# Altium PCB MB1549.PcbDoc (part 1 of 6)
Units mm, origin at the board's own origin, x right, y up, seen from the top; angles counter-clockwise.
Board outline 70 x 133.34 mm, 6 copper layers (Top Layer, Signal Layer 1, Signal Layer 2, Signal Layer 3, Signal Layer 4, Bottom Layer), stack 1.57 mm thick; 289 components, 250 nets, 1288 pads, 875 vias.
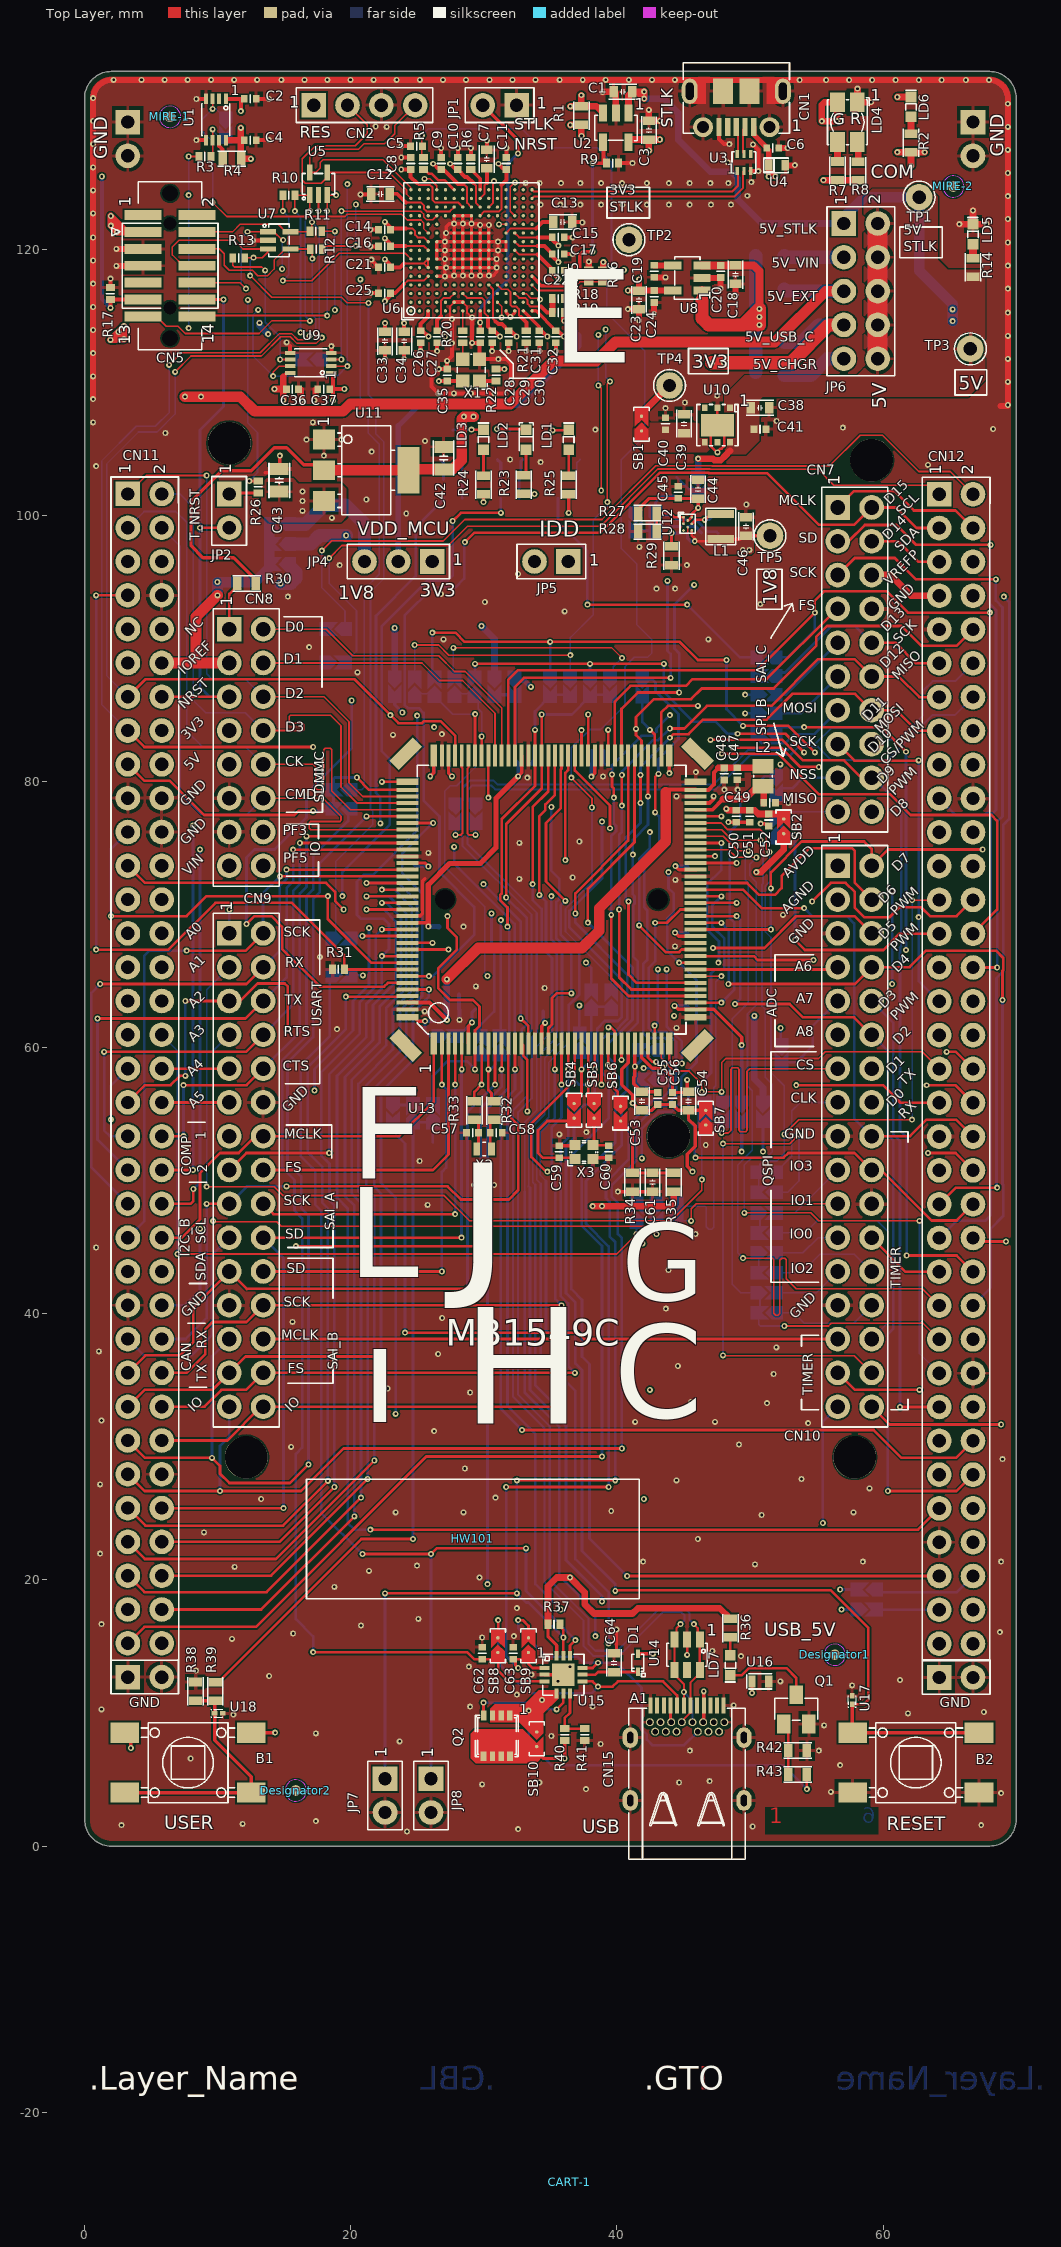
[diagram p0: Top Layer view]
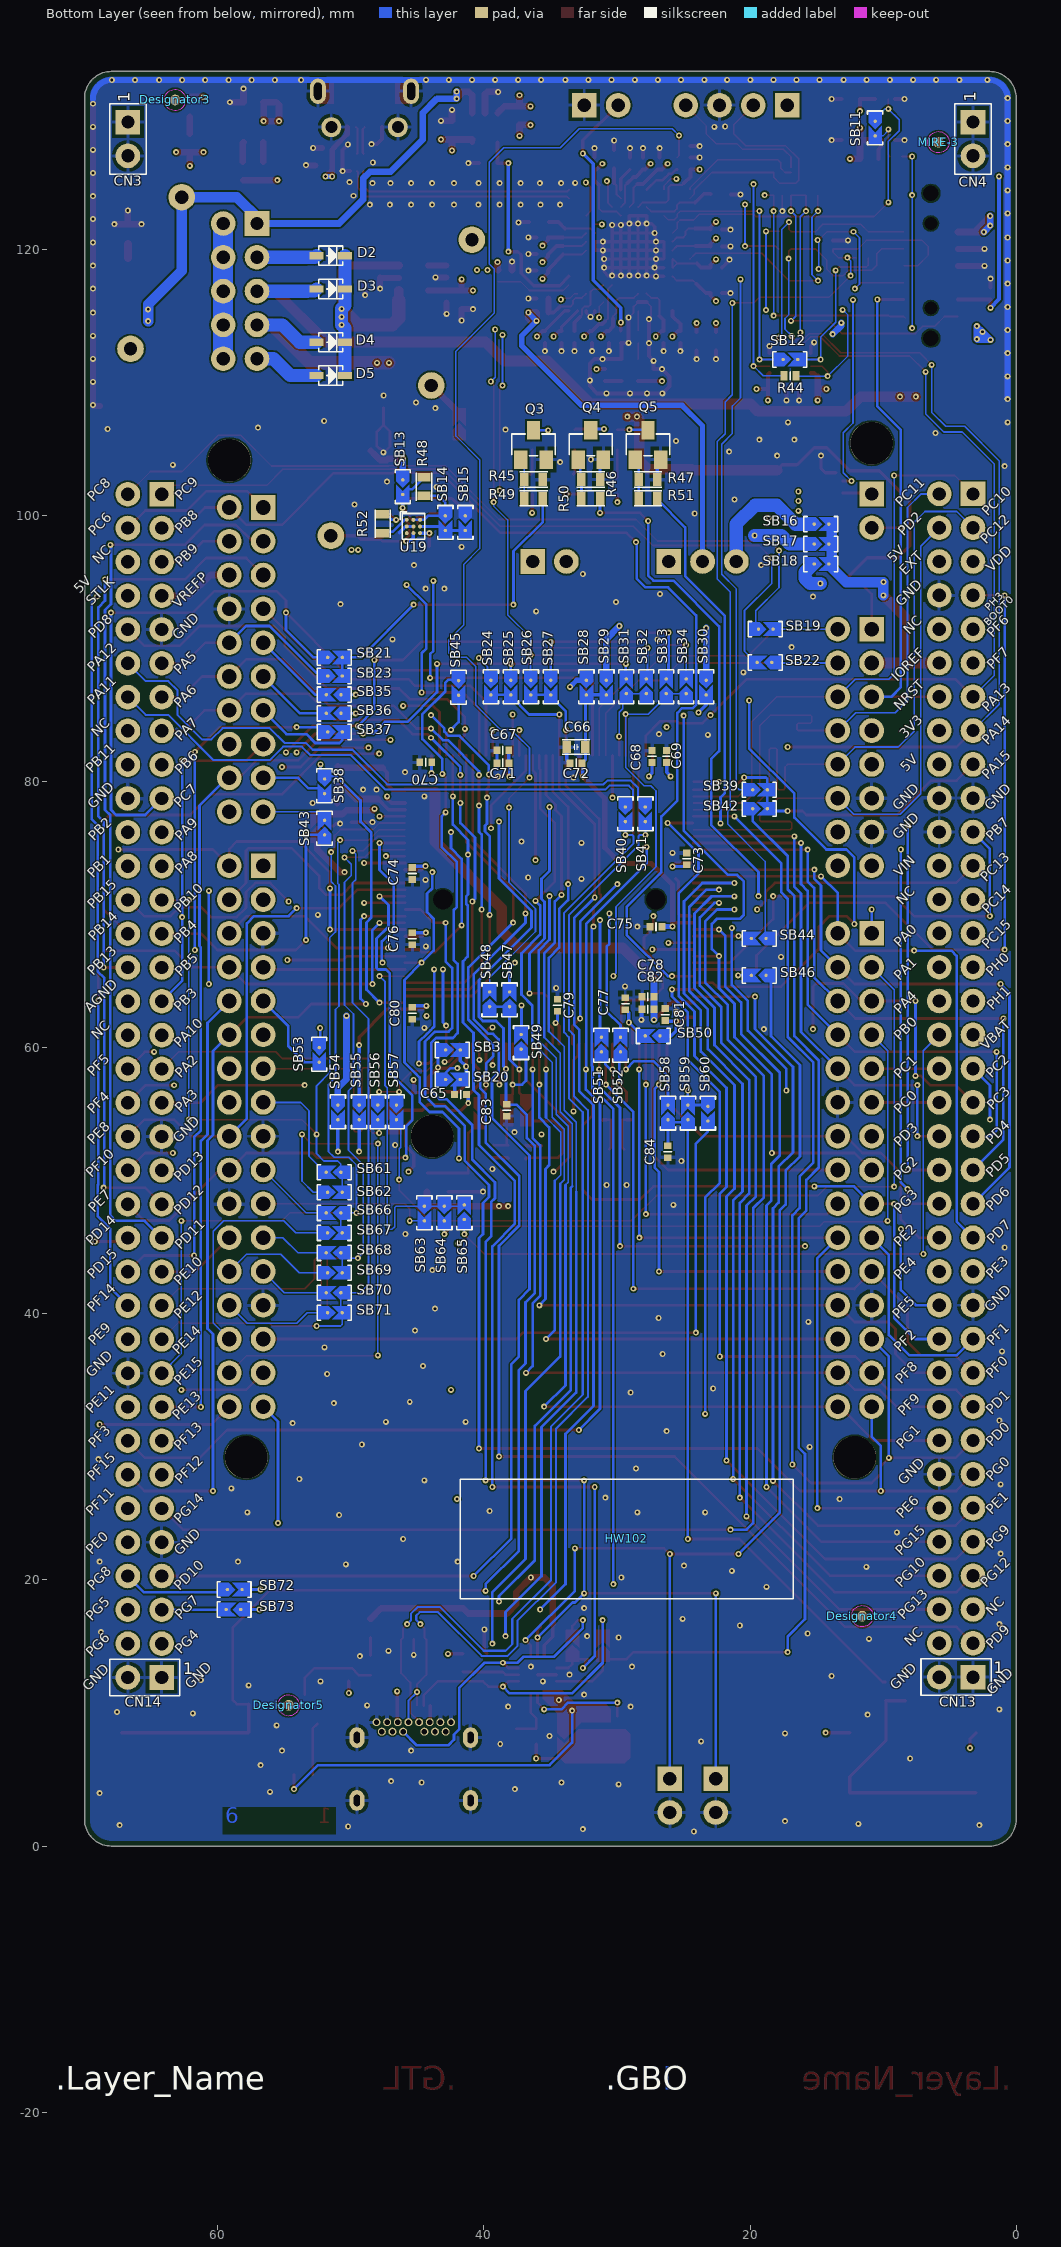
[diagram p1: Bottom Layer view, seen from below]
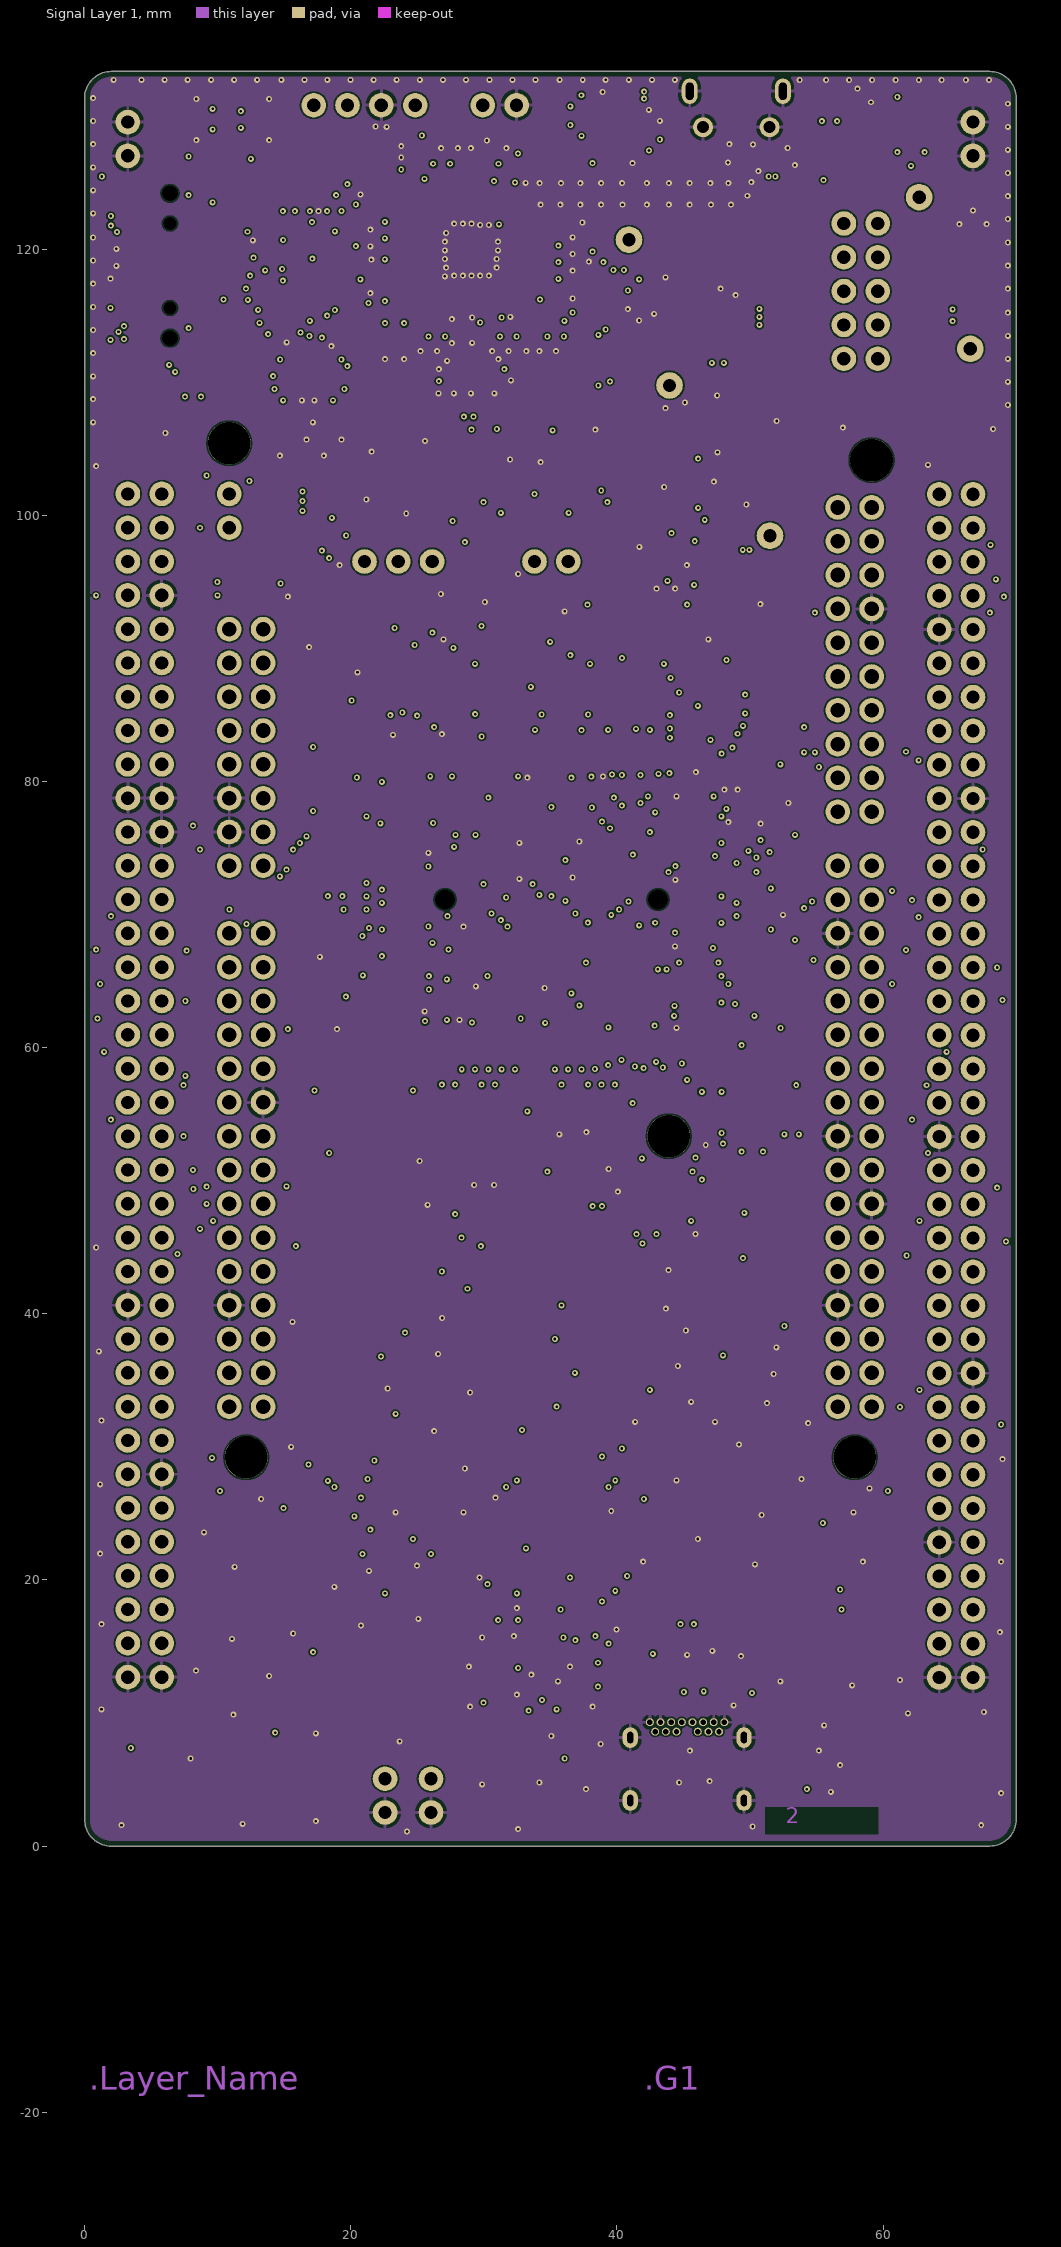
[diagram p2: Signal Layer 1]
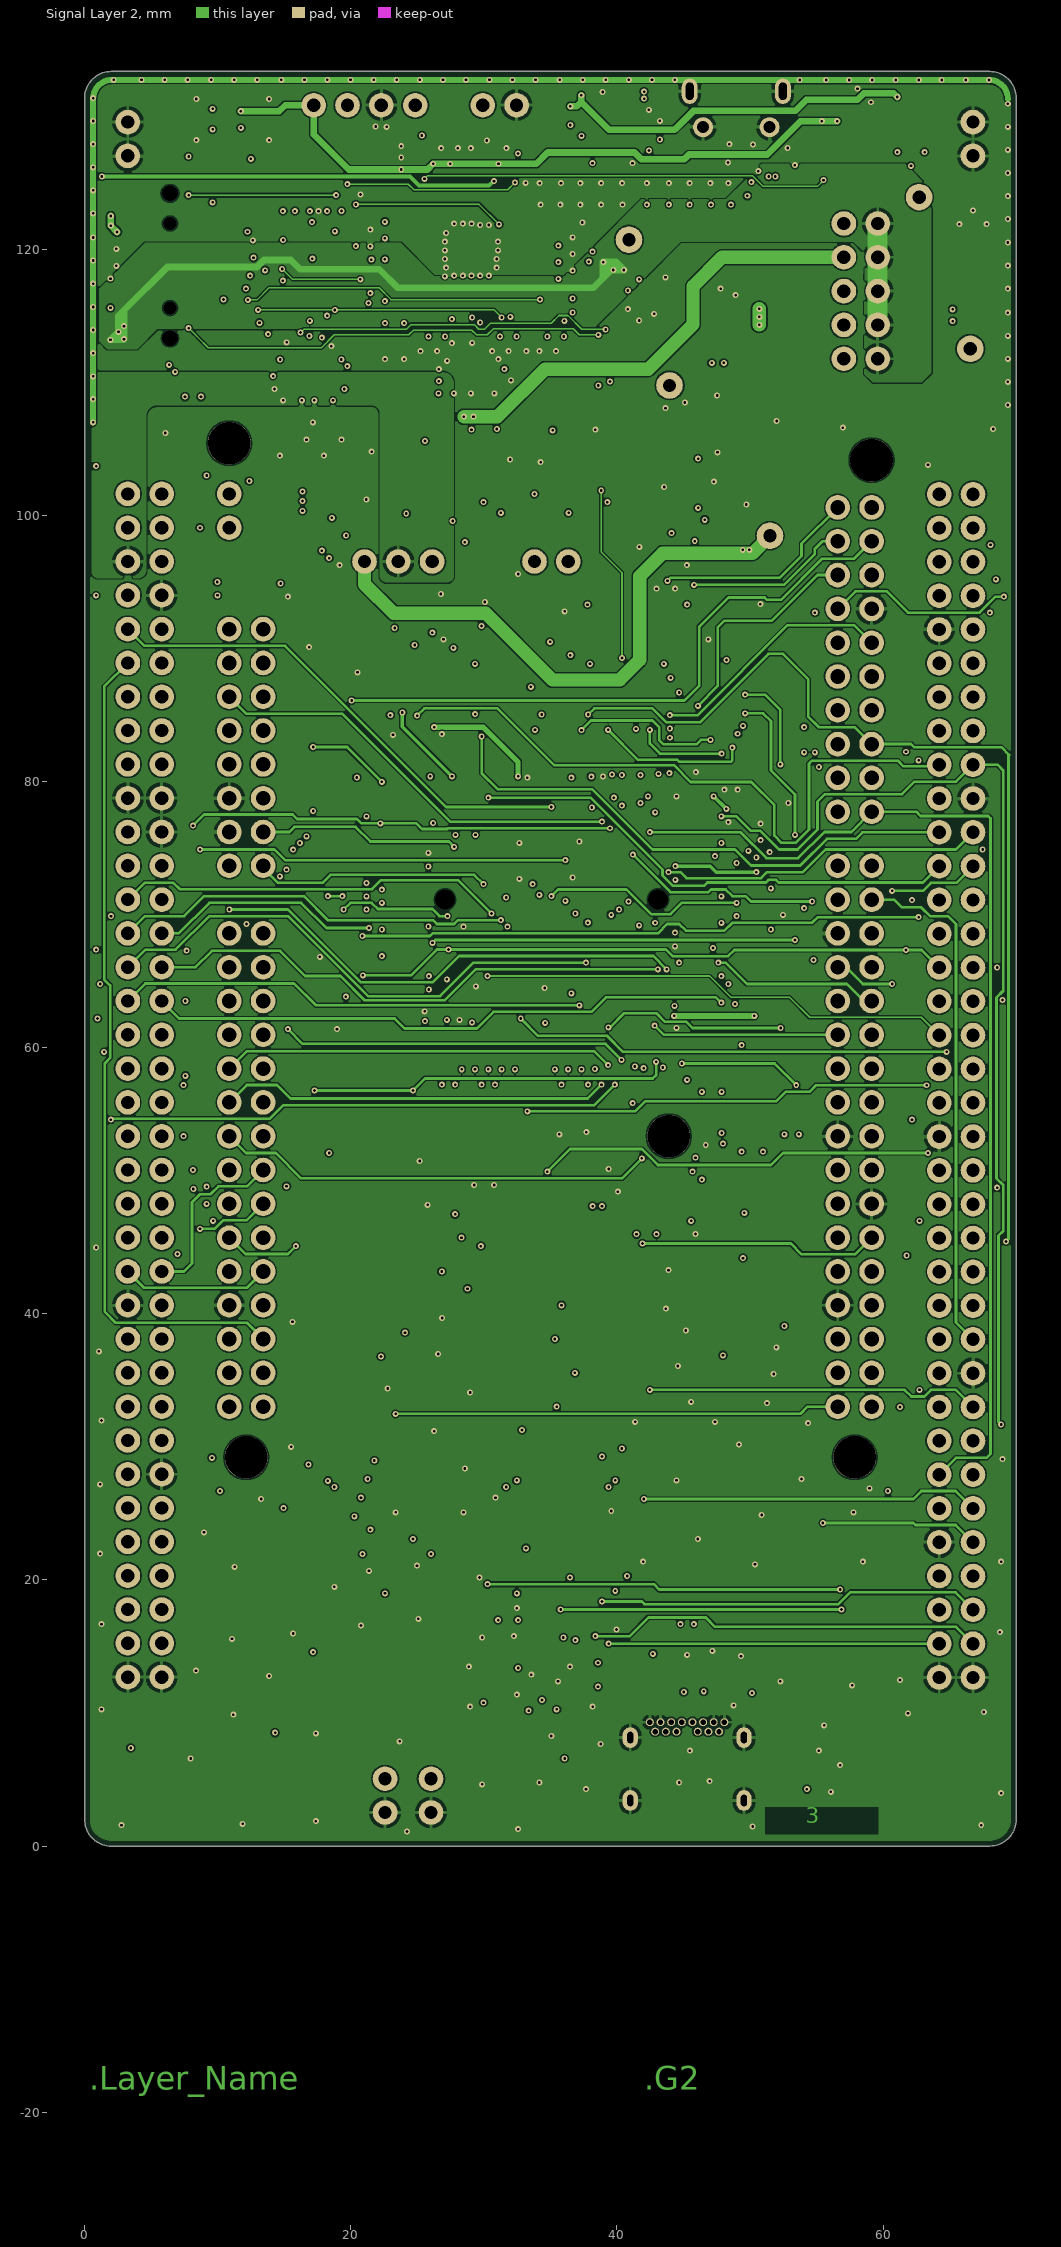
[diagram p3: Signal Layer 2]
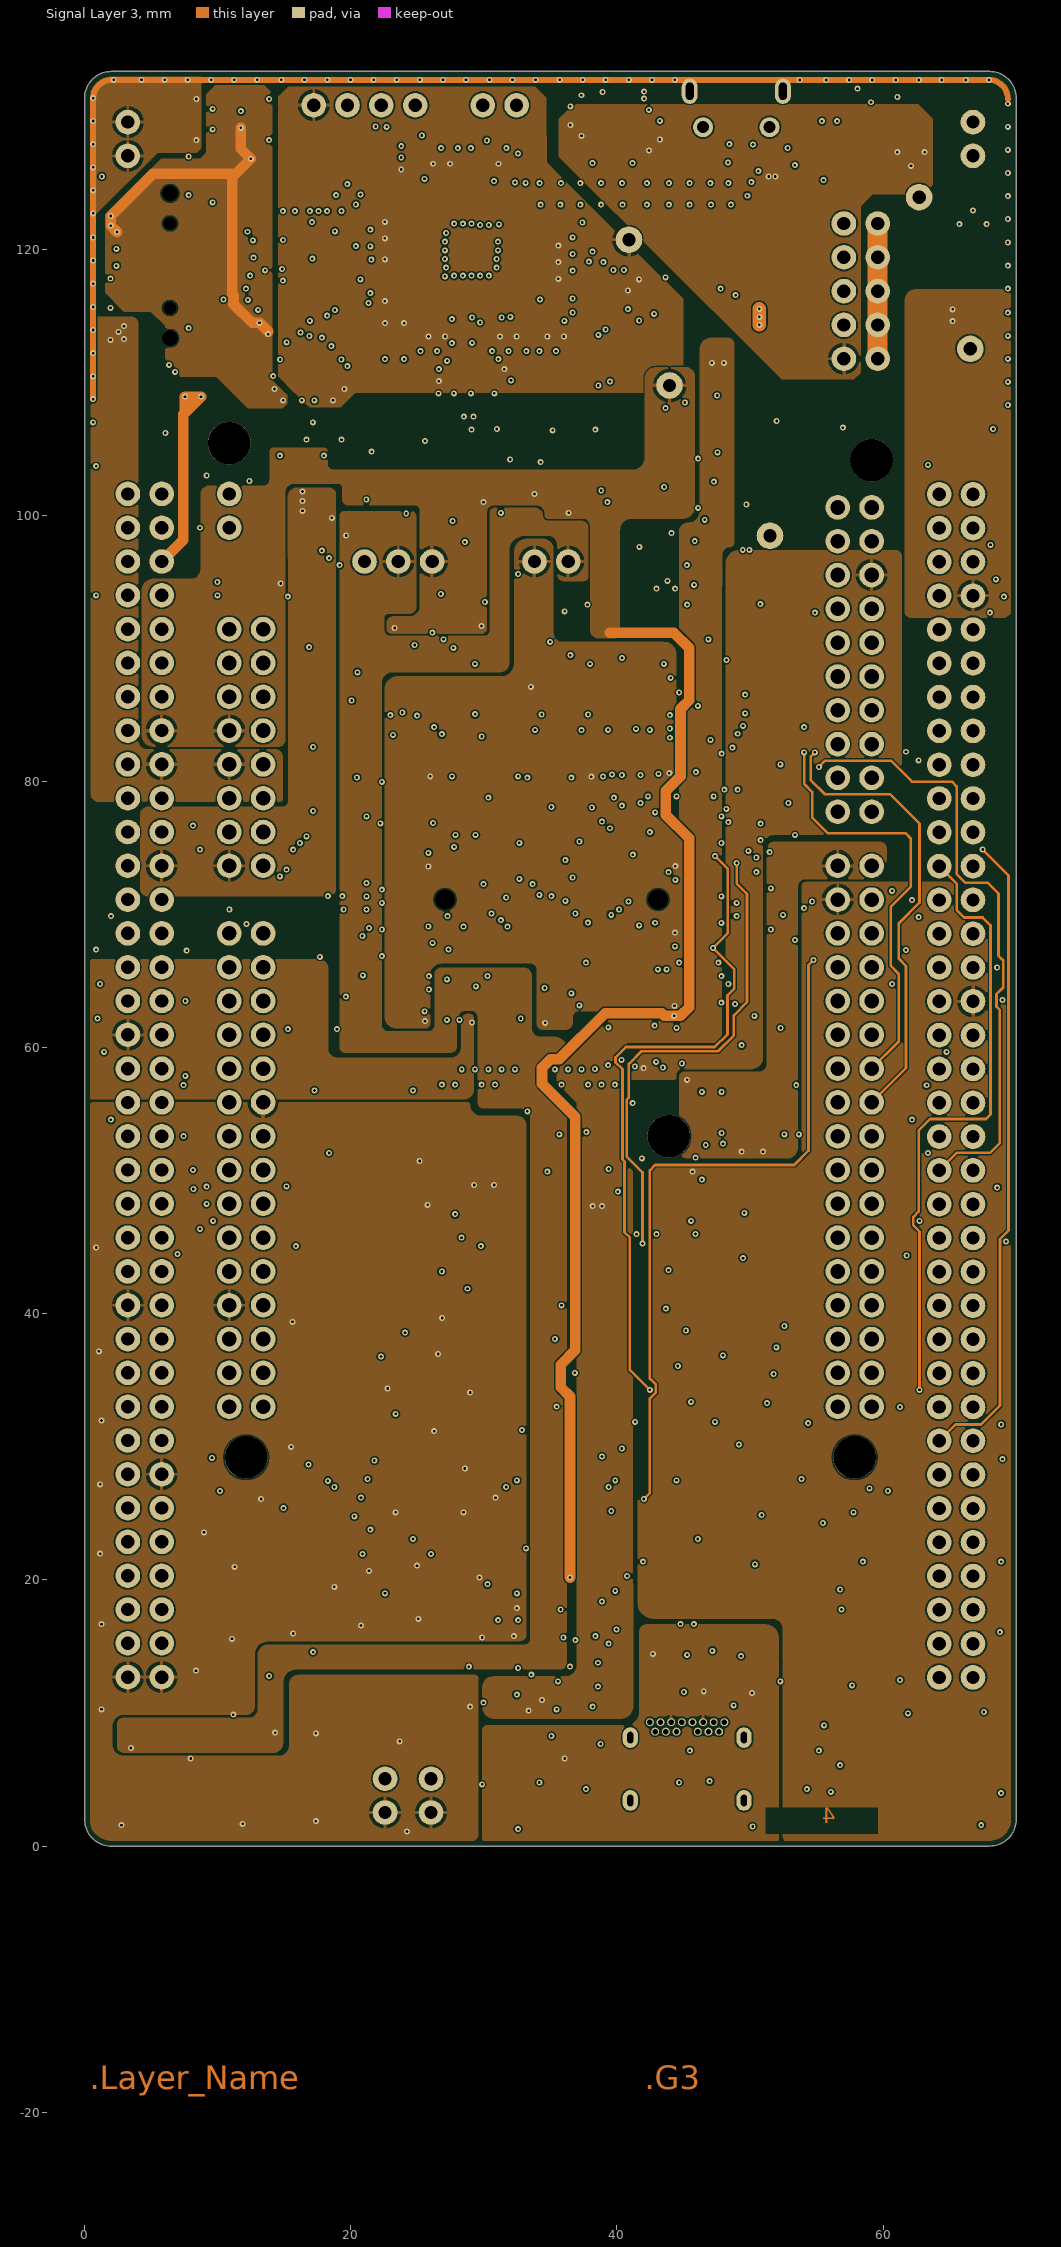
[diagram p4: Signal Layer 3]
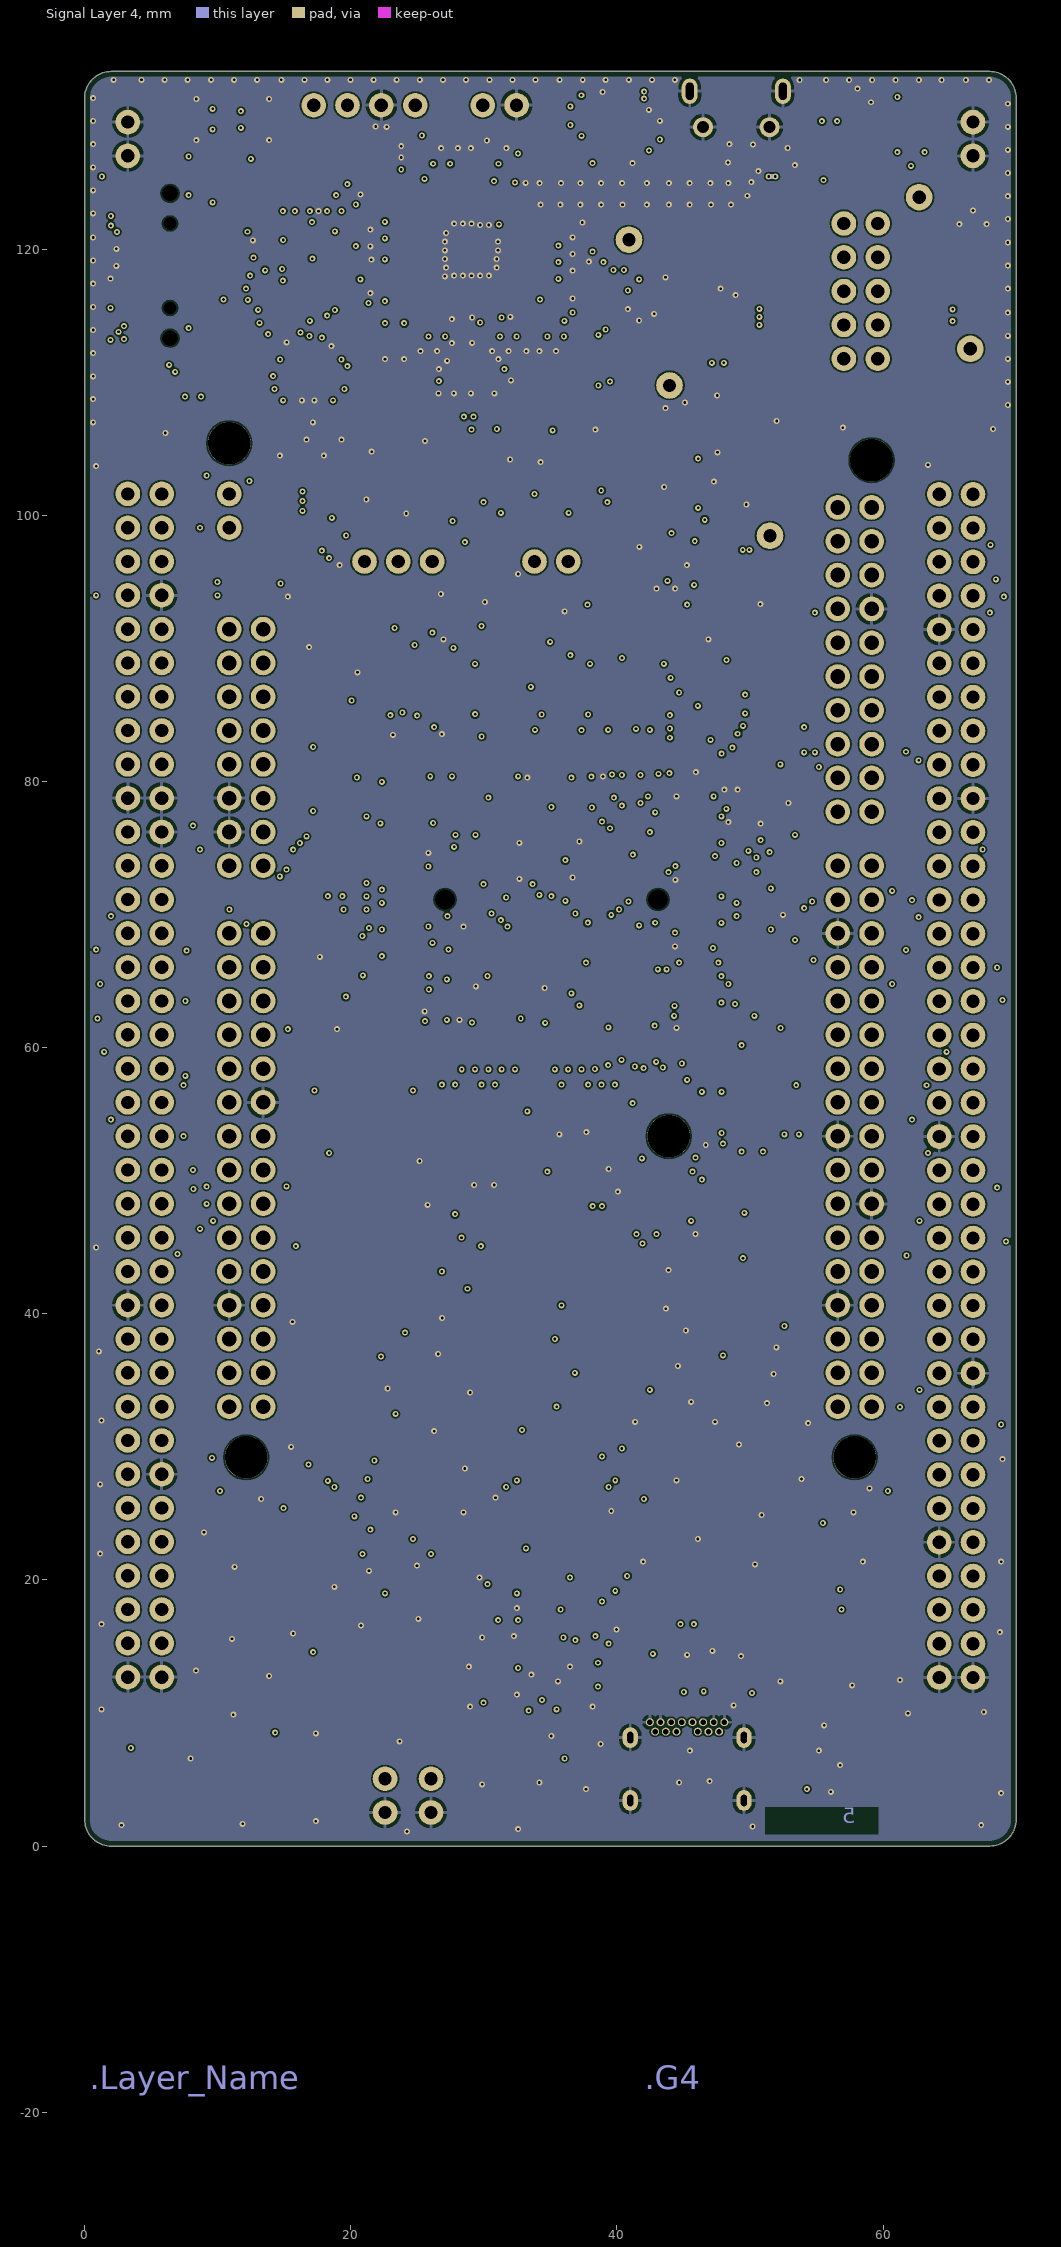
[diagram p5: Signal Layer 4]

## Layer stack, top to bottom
Top Solder: solder mask 0.015, Solder Resist, Dk 3.5
Top Layer: signal copper 0.042
Dielectric 1: core 0.09, FR-4, Dk 4.2
Signal Layer 1: signal copper 0.035
Dielectric 2: prepreg 0.1, Dk 4.2
Signal Layer 2: signal copper 0.035
Dielectric 3: core 0.966, Dk 4.2
Signal Layer 3: signal copper 0.035
Dielectric 4: prepreg 0.1, Dk 4.2
Signal Layer 4: signal copper 0.035
Dielectric 5: core 0.09, Dk 4.2
Bottom Layer: signal copper 0.042
Bottom Solder: solder mask 0.015, Solder Resist, Dk 3.5

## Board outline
0.004,2.002 ccw(c2.004,2.002) 2.004,0.002 2,0.001 68,0.001 68,0.006 ccw(c68,2.006) 70,2.006 70,131.341 ccw(c68,131.341) 68,133.341 2,133.341 ccw(c2,131.341) 0,131.341

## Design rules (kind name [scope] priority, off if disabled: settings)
BoardOutlineClearance "BOTTOM Silksreen clearence" [OnLayer('Bottom Overlay')] p1: gap=0 ignorepadtopadclearanceinfootprint=FALSE
BoardOutlineClearance "TOP Silksreen clearence" [OnLayer('Top Overlay')] p2: gap=0 ignorepadtopadclearanceinfootprint=FALSE
BoardOutlineClearance [All] p3: gap=0.4 ignorepadtopadclearanceinfootprint=FALSE
Clearance Clearance_ALIM [InNetClass('ALIM')] p1: gap=0.127 ignorepadtopadclearanceinfootprint=FALSE except(0.15: Track-Fill SMDPad-Fill THPad-Fill Via-Fill Fill-Fill; 0.2: Arc-Track Arc-THPad Track-Track Track-THPad SMDPad-SMDPad SMDPad-THPad THPad-THPad; 0.3: Track-Poly Poly-Poly)
Clearance [All] p2: gap=0.12 ignorepadtopadclearanceinfootprint=FALSE except(0.2: SMDPad-SMDPad SMDPad-THPad THPad-THPad Via-Via; 0.3: Arc-Fill Track-Fill SMDPad-Fill THPad-Fill Via-Fill Fill-Fill)
ComponentClearance [All] p1 off: gap=0.025 collisioncheckmode=3 verticalgap=2540 showdistances=TRUE
DiffPairsRouting [InDifferentialPairClass('USB')] p1: maxlimit=0.254 minlimit=0.226 mostfreqgap=0.254 toplayer_maxgap=0.226 toplayer_prefgap=0.226 toplayer_minwidth=0.155 toplayer_maxwidth=0.155 toplayer_prefwidth=0.155 midlayer1_mingap=0.254 midlayer1_minwidth=0.381 midlayer1_maxwidth=0.381 midlayer1_prefwidth=0.381 midlayer2_mingap=0.251 midlayer2_maxgap=0.251 midlayer2_prefgap=0.251 midlayer2_minwidth=0.13 midlayer2_maxwidth=0.13 midlayer2_prefwidth=0.13 midlayer3_mingap=0.254 midlayer3_minwidth=0.381 midlayer3_maxwidth=0.381 midlayer3_prefwidth=0.381 midlayer4_mingap=0.254 midlayer4_minwidth=0.381 midlayer4_maxwidth=0.381 midlayer4_prefwidth=0.381 bottomlayer_maxgap=0.226 bottomlayer_prefgap=0.226 bottomlayer_minwidth=0.155 bottomlayer_maxwidth=0.155 bottomlayer_prefwidth=0.155 maxuncoupledlength=12.7
Height [All] p1 off: minheight=0 maxheight=100 prefheight=0.5
HoleSize [All] p1: absolutevalues=TRUE maxlimit=10 minlimit=0.1 maxpercent=80.000 minpercent=20.000
HoleToHoleClearance [All] p1: gap=0.25 allowstackedmicrovias=TRUE
MatchedLengths "Schematic Matched Net Lengths_3" [InNet('USB_DEV_HS_N')] p1: tolerance=2.5 checknetsindiffpair=TRUE checkdiffpairvsdiffpair=FALSE checkxsignals=FALSE checkothers=FALSE
MatchedLengths "Schematic Matched Net Lengths_2" [InNet('USB_DEV_HS_CN_N')] p2: tolerance=0.2 checknetsindiffpair=TRUE checkdiffpairvsdiffpair=FALSE checkxsignals=FALSE checkothers=FALSE
MatchedLengths "Schematic Matched Net Lengths_1" [InNet('USB_DEV_HS_CN_P')] p3: tolerance=0.2 checknetsindiffpair=TRUE checkdiffpairvsdiffpair=FALSE checkxsignals=FALSE checkothers=FALSE
MatchedLengths "Schematic Matched Net Lengths" [InNet('USB_DEV_HS_P')] p4: tolerance=0.2 checknetsindiffpair=TRUE checkdiffpairvsdiffpair=FALSE checkxsignals=FALSE checkothers=FALSE
MatchedLengths MatchedLengths_JTAG [All] p5: tolerance=10 checknetsindiffpair=FALSE checkdiffpairvsdiffpair=TRUE checkxsignals=TRUE checkothers=TRUE
MatchedLengths MatchedLengths_USB [InDifferentialPairClass('USB')] p6: tolerance=2.5 checknetsindiffpair=FALSE checkdiffpairvsdiffpair=TRUE checkxsignals=TRUE checkothers=TRUE
MatchedLengths MatchedLengths_SD_CARD [All] p7: tolerance=10 checknetsindiffpair=FALSE checkdiffpairvsdiffpair=TRUE checkxsignals=TRUE checkothers=TRUE
MatchedLengths MatchedLengths_SPI [InNetClass('SPI')] p8: tolerance=7 checknetsindiffpair=FALSE checkdiffpairvsdiffpair=TRUE checkxsignals=TRUE checkothers=TRUE
MaxMinImpedance "Schematic Impedance Constraint_3" [InNet('USB_DEV_HS_CN_N')] p1: minimum=85,00 maximum=95,00
MaxMinImpedance "Schematic Impedance Constraint_2" [InNet('USB_DEV_HS_CN_P')] p2: minimum=85,00 maximum=95,00
MaxMinImpedance "Schematic Impedance Constraint_1" [InNet('USB_DEV_HS_N')] p3: minimum=85,00 maximum=95,00
MaxMinImpedance "Schematic Impedance Constraint" [InNet('USB_DEV_HS_P')] p4: minimum=85,00 maximum=95,00
MinimumSolderMaskSliver [All] p1: minsoldermaskwidth=0
PlaneClearance [All] p1: clearance=0.5
PlaneConnect [All] p1: planeconnectstyle=Relief reliefexpansion=0.5 reliefentries=4 reliefconductorwidth=0.25 reliefairgap=0.25
PolygonConnect PolygonConnect_NO_TH [IsNamedPolygon('NO_TH')] p1: thpad.connectstyle=Relief thpad.reliefconductorwidth=0.25 thpad.reliefentries=4 thpad.polygonreliefangle="90 Angle" thpad.airgapwidth=0.25 smdpad.connectstyle=Direct smdpad.reliefconductorwidth=0.254 smdpad.reliefentries=4 smdpad.polygonreliefangle="90 Angle" smdpad.airgapwidth=0.254 via.connectstyle=Direct via.reliefconductorwidth=0.254 via.reliefentries=4 via.polygonreliefangle="90 Angle" via.airgapwidth=0.254
PolygonConnect PolygonConnect_1 [All] p2: thpad.connectstyle=Relief thpad.reliefconductorwidth=0.254 thpad.reliefentries=4 thpad.polygonreliefangle="90 Angle" thpad.airgapwidth=0.254 smdpad.connectstyle=Relief smdpad.reliefconductorwidth=0.254 smdpad.reliefentries=4 smdpad.polygonreliefangle="90 Angle" smdpad.airgapwidth=0.254 via.connectstyle=Direct via.reliefconductorwidth=0.254 via.reliefentries=4 via.polygonreliefangle="90 Angle" via.airgapwidth=0.254
RoutingVias [All] p1: holewidth=0.2 width=0.45 viastyle="Through Hole" minholewidth=0.2 minwidth=0.45 maxholewidth=0.2 maxwidth=0.45
SilkToSilkClearance [All] p1: silktosilkclearance=0
SilkToSolderMaskClearance [IsPad] p1: minsilkscreentomaskgap=0 clearancetoexposedcopper=TRUE
SolderMaskExpansion [All] p1: expansion=0.102 istentingtop=FALSE
Width Width_50_ohms [InNetClass('50 ohms')] p1: maxlimit=0.25 minlimit=0.102 preferedwidth=0.25 toplayer_minwidth=0.127 toplayer_maxwidth=0.127 toplayer_prefwidth=0.127 midlayer1_minwidth=0.25 midlayer2_maxwidth=0.102 midlayer2_prefwidth=0.102 midlayer3_minwidth=0.25 midlayer4_minwidth=0.25 bottomlayer_minwidth=0.127 bottomlayer_maxwidth=0.127 bottomlayer_prefwidth=0.127 minimp=50.000000 maximp=50.000000 favimp=50.000000
Width Width_GND [InNetClass('GND')] p2: maxlimit=0.8 minlimit=0.19 preferedwidth=0.25 minimp=50.000000 maximp=50.000000 favimp=50.000000
Width Width_ALIM_150mA [InNetClass('ALIM_150mA')] p3: maxlimit=1 minlimit=0.25 preferedwidth=0.8 minimp=50.000000 maximp=50.000000 favimp=50.000000
Width Width_ALIM_200mA [InNetClass('ALIM_200mA')] p4: maxlimit=1 minlimit=0.25 preferedwidth=0.4 minimp=50.000000 maximp=50.000000 favimp=50.000000
Width Width_ALIM_500mA [InNetClass('ALIM_500mA')] p5: maxlimit=1 minlimit=0.25 preferedwidth=1 minimp=50.000000 maximp=50.000000 favimp=50.000000
Width Width_ALIM_1A [InNetClass('ALIM_1A')] p6: maxlimit=2 minlimit=0.25 preferedwidth=2 minimp=50.000000 maximp=50.000000 favimp=50.000000
Width Width_1 [All] p7: maxlimit=10 minlimit=0.12 preferedwidth=0.12 minimp=50.000000 maximp=50.000000 favimp=50.000000
20 further rules are at their usual default settings.

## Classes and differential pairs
net class PC[0..15]: PC0 PC1 PC2 PC3 PC6 PC7 PC8 PC9 PC10 PC11 PC12 PC13 PC14 PC15
net class PE[0..15]: PE0 PE1 PE2 PE3 PE4 PE5 PE6 PE7 PE8 PE9 PE10 PE11 PE12 PE13 PE14 PE15
polygon class POLY_DIRECT_ALL: NETC906_2_L01_P192
component class U_ARDUINO_extension_connectors: C65 CN7 CN8 CN9 CN10 CN11 CN12 CN13 CN14 HW25 HW26 LD1 Q3 R25 R30 R45 R49 SB16 SB17 SB18 SB19 SB20 SB21 SB22 SB23 SB35 SB36 SB37 SB38 SB43 SB47 SB53 SB56 SB57 SB60 SB61 SB62 SB63 SB64 SB65 SB66 SB67 SB68 SB69 SB70 SB71 SB72
component class U_POWER_BOARD: C38 C39 C40 C41 C42 C43 C44 C45 C46 JP4 JP6 L1 LD5 R14 R27 R28 R29 R48 R52 SB1 SB13 SB14 SB15 SB116 TP3 TP4 TP5 U10 U11 U12 U19
component class U_ST_LINK_V3E: C1 C2 C3 C4 C5 C6 C7 C8 C9 C10 C11 C12 C13 C14 C15 C16 C17 C18 C19 C20 C21 C22 C23 C24 C25 C26 C27 C28 C29 C30 C31 C32 C33 C34 C35 C36 C37 CN1 CN2 CN3 CN4 CN5 D2 D3 D4 D5 D7 HW8 HW9 JP1 JP2 LD4 LD6 R1 R2 R3 R4 R5 R6 R7 R8 R9 R10 R11 R12 R13 R15 R16 R17 R18 R19 R20 R21 R22 R26 R44 SB11 SB12 TP1 TP2 U1 U2 U3 U4 U5 U6 U7 U8 U9 X1
component class U_STM32_microcontroller_IOs: B1 B2 C57 C58 C59 C60 C83 C84 HW11 HW17 HW18 LD2 LD3 Q4 Q5 R23 R24 R31 R32 R33 R38 R39 R46 R47 R50 R51 SB4 SB5 SB6 SB24 SB25 SB26 SB27 SB31 SB32 SB33 SB34 SB39 SB40 SB41 SB42 SB44 SB47 SB48 SB49 SB51 SB52 SB58 SB60 U13 U17 U18 X2 X3
component class U_STM32_microcontroller_power: C47 C48 C49 C50 C51 C52 C53 C54 C55 C56 C66 C67 C68 C69 C70 C71 C72 C73 C74 C75 C76 C77 C78 C79 C80 C81 C82 JP5 L2 SB2 SB3 SB7 SB28 SB29 SB30 SB52 SB54 SB57
component class U_USB_Type_C: C61 C62 C63 C64 CN15 D1 HW23 HW24 LD7 Q1 Q2 R34 R35 R36 R37 R40 R41 R42 R43 R108 SB8 SB9 SB10 U14 U15 U16
component class U_MB1549_Top: HW100 HW101 HW102
net class PA[0..15]: PA0 PA1 PA2 PA3 PA4 PA5 PA6 PA7 PA8 PA9 PA10 PA11 PA12 PA13 PA14 PA15
net class PB[0..15]: PB0 PB1 PB2 PB3 PB4 PB5 PB6 PB7 PB8 PB9 PB10 PB11 PB12 PB13 PB14 PB15
net class PD[0..15]: PD0 PD1 PD2 PD3 PD4 PD5 PD6 PD7 PD8 PD9 PD10 PD11 PD12 PD13 PD14 PD15
net class PF[0..15]: PF0 PF1 PF2 PF3 PF4 PF5 PF6 PF7 PF8 PF9 PF10 PF11 PF12 PF13 PF14 PF15
net class PG[0..15]: PG0 PG1 PG2 PG3 PG4 PG5 PG6 PG7 PG9 PG10 PG11 PG12 PG13 PG14 PG15
net class PH[0..3]: PH0 PH1 PH2 PH3
differential pair USB_FS: +USB_FS_P -USB_FS_N
differential pair USB_DEV_HS_CN: +USB_DEV_HS_CN_P -USB_DEV_HS_CN_N
differential pair USB_DEV_HS: +USB_DEV_HS_P -USB_DEV_HS_N

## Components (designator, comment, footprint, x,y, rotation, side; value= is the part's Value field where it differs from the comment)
B1 "" SWI_WEALTHMETAL_TD-0341_4P_BLUE 7.771,6.275 r270 top value=SW_BLUE
B2 "" SWI_WEALTHMETAL_TD-0341_4P_BLACK 62.457,6.275 r270 top value=SW_BLACK
C1 "Capacitor" C0603 40.448,131.82 r0 top value=1uF
C2 "" C0402 12.441,131.279 r180 top value=100nF
C3 "Capacitor" C0603 42.396,128.927 r270 top value=1uF
C4 "" C0402 12.441,128.179 r0 top value=100nF
C5 "Capacitor" C0402 24.941,127.729 r0 top value=20pF
C6 "Capacitor" C0402 51.699,127.593 r180 top value=100pF
C7 "Capacitor" C0603 30.216,126.754 r270 top value=2.2uF
C8 "" C0402 24.491,126.429 r270 top value=100nF
C9 "" C0402 26.791,126.429 r270 top value=100nF
C10 "" C0402 28.041,126.429 r270 top value=100nF
C11 "" C0402 31.691,126.429 r270 top value=100nF
C12 "Capacitor" C0603 22.225,124.125 r0 top value=2.2uF
C13 "Capacitor" C0603 35.925,122.025 r180 top value=2.2uF
C14 "" C0402 22.541,121.454 r0 top value=100nF
C15 "" C0402 35.591,120.879 r180 top value=100nF
C16 "" C0402 22.541,120.204 r0 top value=100nF
C17 "" C0402 35.591,119.629 r180 top value=100nF
C18 "Capacitor" C0603 48.916,118.079 r90 top value=1uF
C19 "Capacitor" C0402 42.791,118.329 r90 top value=10nF
C20 "" C0402 47.794,118.32 r90 top value=100nF
C21 "" C0402 22.541,118.629 r0 top value=100nF
C22 "" C0402 35.591,118.379 r180 top value=100nF
C23 "Capacitor" C0603 41.666,116.179 r90 top value=1uF
C24 "" C0402 42.791,116.429 r90 top value=100nF
C25 "" C0402 22.541,116.679 r0 top value=100nF
C26 "" C0402 25.241,113.404 r90 top value=100nF
C27 "" C0402 26.491,113.404 r90 top value=100nF
C28 "" C0402 29.716,113.404 r90 top value=100nF
C29 "" C0402 30.616,113.404 r90 top value=100nF
C30 "" C0402 31.866,113.404 r90 top value=100nF
C31 "" C0402 34.166,113.404 r90 top value=100nF
C32 "" C0402 35.416,113.404 r90 top value=100nF
C33 "Capacitor" C0603 22.566,113.079 r90 top value=4.7uF
C34 "Capacitor" C0603 24.016,113.079 r90 top value=1uF
C35 "" C0402 27.241,110.529 r270 top value=100nF
C36 "" C0402 15.616,109.479 r0 top value=100nF
C37 "" C0402 17.966,109.479 r0 top value=100nF
C38 "Capacitor" C0603 50.745,108.071 r180 top value=1uF
C39 "Capacitor" C0603 45.045,106.871 r270 top value=1uF
C40 "" C0402 43.645,106.871 r270 top value=100nF
C41 "" C0402 50.745,106.471 r180 top value=100nF
C42 "" C0805 26.974,104.294 r270 top value=10uF
C43 "" C0805 14.629,102.617 r270 top value=10uF
C44 "" C0603 46.095,101.956 r270 top value=10uF
C45 "" C0402 44.6,101.725 r270 top value=100nF
C46 "" C0603 49.695,99.156 r270 top value=10uF
C47 "Capacitor" C0402 49.05,80.575 r90 top value=2.2uF
C48 "Capacitor" C0402 48.05,80.561 r90 top value=2.2uF
C49 "" C0402 51.47,78.381 r180 top value=100pF
C50 "" C0402 48.97,77.381 r90 top value=10uF
C51 "" C0402 49.97,77.381 r90 top value=10uF
C52 "" C0402 51.4,77.1 r90 top value=100nF
C53 "Capacitor" C0603 41.87,55.981 r270 top value=1uF
C54 "Capacitor" C0603 45.37,55.981 r270 top value=1uF
C55 "" C0402 43.07,56.181 r90 top value=100nF
C56 "" C0402 44.17,56.181 r90 top value=100nF
C57 "Capacitor" C0402 29.15,53.6 r180 top value=1.3pF
C58 "Capacitor" C0402 30.925,53.6 r0 top value=1.3pF
C59 "Capacitor" C0402 35.67,52.181 r90 top value=6.8pF
C60 "Capacitor" C0402 39.37,52.181 r270 top value=6.8pF
C61 "" C0603 42.67,49.881 r90 top value=10pF
C62 "Capacitor" C0402 29.875,14.5 r270 top value=330pF
C63 "Capacitor" C0402 32.2,14.5 r270 top value=330pF
C64 "Capacitor" C0603 39.77,13.781 r270 top value="100nF, 50V"
C65 "" C0402 41.75,56.475 r0 bottom value=100nF
C66 "Capacitor" C0603 33.07,82.581 r180 bottom value=4.7uF
C67 "" C0402 38.575,82.325 r180 bottom value=10uF
C68 "" C0402 27.37,81.881 r270 bottom value=100nF
C69 "" C0402 26.27,81.881 r270 bottom value=100nF
C70 "" C0402 44.375,81.425 r180 bottom value=100nF
C71 "" C0402 38.57,81.381 r180 bottom value=100nF
C72 "" C0402 33.07,81.381 r180 bottom value=100nF
C73 "" C0402 24.77,74.181 r270 bottom value=100nF
C74 "" C0402 45.37,73.081 r90 bottom value=100nF
C75 "" C0402 27.07,69.081 r180 bottom value=100nF
C76 "" C0402 45.37,68.181 r90 bottom value=100nF
C77 "" C0402 29.375,63.3 r270 bottom value=100nF
C78 "Capacitor" C0402 27.675,63.825 r180 bottom value=2.2uF
C79 "" C0402 34.47,63.181 r270 bottom value=100nF
C80 "" C0402 45.37,62.581 r90 bottom value=100nF
C81 "" C0402 26.37,62.481 r270 bottom value=100nF
C82 "Capacitor" C0402 27.675,62.875 r180 bottom value=2.2uF
C83 "" C0402 38.279,55.296 r90 bottom value=100nF
C84 "" C0402 26.17,52.181 r90 bottom value=100nF
CART-1 "Comment" Sheetbox_6L2S -8.63,-30.519 r0 top
CN1 "USB_uB_105017.0001" CON_USBMICROB_MOLEX_105017-0001_H2P90 48.966,133.308 r180 top value=USB_uB_105017-0001
CN2 "Header 4x1" CON_SAMTEC_TSW-104-07-G-S 21.026,130.809 r0 top
CN3 "Jumper_Header 2x1" CON_SAMTEC_TSW-102-09-X-S 66.746,128.269 r270 bottom value="Header 2x1 16mm"
CN4 "Jumper_Header 2x1" CON_SAMTEC_TSW-102-09-X-S 3.246,128.269 r270 bottom value="Header 2x1 16mm"
CN5 "Header 7x2" CON_STDC14_Receiver_MEDIUM_WITH_MIPI10_3D 6.421,118.744 r270 top value="MIPI10 on STDC14 footprint"
CN7 "" CON_SAMTEC_SSW-110-23-X-D_N144_ARD 57.86,89.155 r90 top value="Socket 10x2_N144_ARD"
CN8 "" CON_SAMTEC_SSW-108-23-X-D_N144_ARD 12.14,82.551 r90 top value="Socket 8x2_N144_ARD"
CN9 "" CON_SAMTEC_SSW-115-23-X-D_N144_ARD 12.14,50.801 r90 top value="Socket 15x2_N144_ARD"
CN10 "" CON_SAMTEC_SSW-117-23-X-D_N144_ARD 57.86,53.341 r90 top value="Socket 17x2_N144_ARD"
CN11 "Header 35x2" CON_SAMTEC_TSW-135-07-X-D 4.52,58.421 r270 top
CN12 "Header 35x2" CON_SAMTEC_TSW-135-07-X-D 65.48,58.396 r270 top
CN13 "" CON_SAMTEC_TSW-102-09-X-S 4.52,12.701 r0 bottom value="Header 2x1 16mm"
CN14 "" CON_SAMTEC_TSW-102-09-X-S 65.48,12.676 r0 bottom value="Header 2x1 16mm"
CN15 "USB_TYPE_C_Receptacle_317JD24BZTF3K3C3" CON_USB-TYPEC_COXOC_317JD24BZTF3K3C3 45.27,-0.019 r0 top value=317JD24BZTF3K3C3
D1 "SCHOTTKY_1A_2K" DIO_SOD523_1A_2K 41.57,13.781 r270 top value=BAT54KFILM
D2 "BAT60JFILM" DIO_SOD323 51.5,119.5 r180 bottom
D3 "BAT60JFILM" DIO_SOD323 51.5,117 r180 bottom
D4 "BAT60JFILM" DIO_SOD323 51.5,113 r180 bottom
D5 "BAT60JFILM" DIO_SOD323 51.5,110.5 r180 bottom
Designator1 "Comment" MIRE_PLACE_SMD_0P8MM 56.37,14.381 r0 top
Designator2 "Comment" MIRE_PLACE_SMD_0P8MM 15.87,4.181 r0 top
Designator3 "Comment" MIRE_PLACE_SMD_0P8MM 63.2,131.2 r180 bottom
Designator4 "Comment" MIRE_PLACE_SMD_0P8MM 11.57,17.281 r180 bottom
Designator5 "Comment" MIRE_PLACE_SMD_0P8MM 54.67,10.581 r180 bottom
HW101 "STICKER_BOARD_REF" STICKER_25X9 29.17,23.081 r0 top value="MBxxxxy-zz syywwxxxxx"
HW102 "STICKER_BOARD_CPN" STICKER_25X9 29.27,23.081 r180 bottom value="Board CPN"
JP1 "Jumper_Header 2x1" CON_SAMTEC_TSW-102-07-G-S 31.186,130.809 r180 top value="Shunt not fitted"
JP2 "Jumper_Header 2x1 Fitted" CON_SAMTEC_TSW-102-07-G-S 10.866,100.329 r270 top value="Shunt Fitted"
JP4 "" CON_SAMTEC_TSW-103-07-F-S 23.57,96.521 r180 top value="Shunt Fitted 1-2"
JP5 "" CON_SAMTEC_TSW-102-07-G-S 35.07,96.521 r180 top value="Shunt Fitted"
JP6 "" CON_SAMTEC_TSW-105-07-X-D 58.32,116.839 r270 top value="Shunt Fitted 1-2"
JP7 "Jumper_Header 2x1" CON_SAMTEC_TSW-102-07-G-S 22.575,3.8 r270 top value="Shunt not fitted"
JP8 "Jumper_Header 2x1" CON_SAMTEC_TSW-102-07-G-S 26.025,3.8 r270 top value="Shunt not fitted"
L1 "" IND_TDK_VLS252010HBX-1 47.795,99.156 r270 top value="2.2uH 2.6A 0.100R"
L2 "Inductor" L0805_H0P9 50.97,80.381 r270 top value=2.2uH
LD1 "" LED_0603_GREEN 36.37,105.681 r90 top value=GREEN
LD2 "" LED_0603_VISHAY_VLMB1300-GS08_BLUE_1A2K_H0P8 33.17,105.681 r90 top value=BLUE
LD3 "LED_red" LED_0603_RED 29.97,105.681 r90 top value=RED
LD4 "LD_BICOLOR_CMS" LED_BI-GR_HSMF-A201-A00J1 57.316,129.529 r180 top
LD5 "" LED_0603_GREEN 66.746,121.119 r90 top value=GREEN
LD6 "LED_red" LED_0603_RED 62.091,130.679 r90 top value=RED
LD7 "" LED_0603_GREEN 48.52,13.581 r270 top value=GREEN
MIRE-1 "Comment" MIRE_PLACE_SMD_0P8MM 6.416,129.929 r0 top
MIRE-2 "Comment" MIRE_PLACE_SMD_0P8MM 65.275,124.7 r0 top
MIRE-3 "Comment" MIRE_PLACE_SMD_0P8MM 5.841,128.029 r180 bottom
Q1 "" NPN_SOT23 53.47,10.281 r0 top value=9013-SOT23
Q2 "STL11N3LLH6" MOS_POWERFLAT_3P3X3P3_P065 30.97,8.281 r180 top
Q3 "" NPN_SOT23 36.27,105.281 r180 bottom value=9013-SOT23
Q4 "" NPN_SOT23 31.97,105.281 r180 bottom value=9013-SOT23
Q5 "" NPN_SOT23 27.67,105.281 r180 bottom value=9013-SOT23
R1 "Resistor" R0603 37.325,130.029 r270 top value=100K
R2 "Resistor" R0603 62.091,127.979 r270 top value=1K
R3 "Resistor" R0402 9.041,126.954 r0 top value=47R
R4 "Resistor" R0603 11.066,126.779 r0 top value=100K
R5 "Resistor" R0402 25.466,126.429 r90 top value=100R
R6 "Resistor" R0402 29.016,126.429 r270 top value=3K
R7 "Resistor" R0603 56.566,125.877 r270 top value=330R
R8 "Resistor" R0603 58.116,125.852 r270 top value=330R
R9 "Resistor" R0402 39.673,126.459 r0 top value=10K
R10 "Resistor" R0402 15.35,124.05 r0 top value=47R
R11 "Resistor" R0402 17.375,121.325 r0 top value=47R
R12 "Resistor" R0402 17.4,119.975 r180 top value=47R
R13 "Resistor" R0402 11.575,119.325 r180 top value=47R
R14 "" R0603 66.746,118.619 r270 top value=1K
R15 "Resistor" R0402 37.891,117.979 r270 top value=4K7
R16 "Resistor" R0402 38.941,117.979 r270 top value=2K7
R17 "Resistor" R0402 1.941,116.654 r270 top value=100R
R18 "Resistor" R0402 35.591,116.279 r0 top value=4K7
R19 "Resistor" R0402 35.591,115.229 r0 top value=4K7
R20 "Resistor" R0402 28.416,113.404 r90 top value=100R
R21 "Resistor" R0402 33.191,113.404 r90 top value=10K
R22 "Resistor" R0402 30.916,110.529 r90 top value=10K
R23 "" R0603 33,102.3 r90 top value=680R
R24 "" R0603 29.97,102.281 r90 top value=1K
R25 "" R0603 36.37,102.281 r270 top value=510R
R26 "Resistor" R0402 13.05,102.125 r270 top value=47R
R27 "" R0603 42.295,100.156 r180 top value=0R
R28 "" R0603 42.295,98.756 r180 top value=0R
R29 "" R0603 44.095,96.956 r270 top value=19K6
R30 "" R0603 12.17,94.881 r0 top value=1K
R31 "Resistor" R0402 19.07,65.881 r180 top value=10K
R32 "" R0603 29.287,55.277 r270 top value=0R
R33 "" R0603 30.786,55.27 r270 top value=0R
R34 "" R0603 41.17,49.881 r90 top value=49K9
R35 "" R0603 44.27,49.881 r270 top value=330K
R36 "" R0603 48.52,16.381 r270 top value=510R
R37 "Resistor" R0402 35.27,16.681 r180 top value=10K
R38 "" R0603 8.33,11.634 r270 top value=100K
R39 "" R0603 9.82,11.631 r270 top value=330R
R40 "Resistor" R0402 36.07,8.381 r90 top value=10K
R41 "Resistor" R0402 37.57,8.381 r90 top value=2K7
R42 "" R0603 53.57,7.181 r180 top value=22K
R43 "" R0603 53.57,5.381 r180 top value=47K
R44 "Resistor" R0402 16.991,110.479 r0 bottom value=100R
R45 "" R0603 36.27,102.681 r0 bottom value=100K
R46 "" R0603 31.97,102.681 r0 bottom value=100K
R47 "" R0603 27.67,102.681 r0 bottom value=100K
R48 "" R0603 44.5,102.15 r270 bottom value=0R
R49 "" R0603 36.27,101.281 r0 bottom value=47K
R50 "" R0603 31.97,101.281 r0 bottom value=47K
R51 "" R0603 27.67,101.281 r0 bottom value=47K
R52 "" R0603 47.595,99.356 r270 bottom value=0R
SB1 "" SOLDER-BRIDGE_R0603-0R 41.845,106.831 r90 top
SB2 "" SOLDER-BRIDGE_R0603-0R 52.525,76.575 r90 top
SB3 "" SOLDER-BRIDGE_R0603-0R 42.375,59.825 r180 bottom
SB4 "" SOLDER-BRIDGE_R0603-0R 36.78,55.296 r270 top locked
SB5 "" SOLDER-BRIDGE_R0603-0R 38.279,55.296 r270 top locked
SB6 "" SOLDER-BRIDGE_R0603-0R 40.27,55.081 r270 top
SB7 "" SOLDER-BRIDGE_R0603-0R 46.67,54.681 r90 top
SB8 "" SOLDER-BRIDGE_R0603-0R 31.05,15.05 r90 top
SB9 "" SOLDER-BRIDGE_R0603-0R 33.35,15.05 r90 top
SB10 "" SOLDER-BRIDGE_R0603-0R 33.97,8.081 r270 top
SB11 "SB_ON" SOLDER-BRIDGE_R0603-0R 10.6,129.1 r270 bottom
SB12 "SB_ON" SOLDER-BRIDGE_R0603-0R 17.016,111.704 r180 bottom
SB13 "" SOLDER-BRIDGE_R0603-0R 46.095,102.156 r270 bottom
SB14 "" SOLDER-BRIDGE_R0603-0R 42.895,99.456 r270 bottom
SB15 "" SOLDER-BRIDGE_R0603-0R 41.395,99.456 r270 bottom
SB16 "" SOLDER-BRIDGE_R0603-0R 14.681,99.332 r180 bottom
SB17 "" SOLDER-BRIDGE_R0603-0R 14.681,97.832 r180 bottom
SB18 "" SOLDER-BRIDGE_R0603-0R 14.681,96.332 r180 bottom
SB19 "" SOLDER-BRIDGE_R0603-0R 18.87,91.441 r180 bottom
SB20 "" SOLDER-BRIDGE_R0603-0R 42.375,57.6 r180 bottom
SB21 "" SOLDER-BRIDGE_R0603-0R 51.237,89.318 r180 bottom
SB22 "" SOLDER-BRIDGE_R0603-0R 18.87,88.941 r0 bottom
SB23 "" SOLDER-BRIDGE_R0603-0R 51.237,87.918 r180 bottom
SB24 "" SOLDER-BRIDGE_R0603-0R 39.475,87.1 r270 bottom
SB25 "" SOLDER-BRIDGE_R0603-0R 37.975,87.1 r270 bottom
SB26 "" SOLDER-BRIDGE_R0603-0R 36.475,87.1 r270 bottom
SB27 "" SOLDER-BRIDGE_R0603-0R 34.975,87.1 r270 bottom
SB28 "" SOLDER-BRIDGE_R0603-0R 32.3,87.1 r270 bottom
SB29 "" SOLDER-BRIDGE_R0603-0R 30.8,87.1 r270 bottom
SB30 "" SOLDER-BRIDGE_R0603-0R 23.3,87.1 r270 bottom
SB31 "" SOLDER-BRIDGE_R0603-0R 29.3,87.1 r90 bottom
SB32 "" SOLDER-BRIDGE_R0603-0R 27.8,87.1 r90 bottom
SB33 "" SOLDER-BRIDGE_R0603-0R 26.3,87.1 r90 bottom
SB34 "" SOLDER-BRIDGE_R0603-0R 24.8,87.1 r90 bottom
SB35 "" SOLDER-BRIDGE_R0603-0R 51.237,86.518 r0 bottom
SB36 "" SOLDER-BRIDGE_R0603-0R 51.237,85.118 r0 bottom
SB37 "" SOLDER-BRIDGE_R0603-0R 51.237,83.718 r180 bottom
SB38 "" SOLDER-BRIDGE_R0603-0R 51.97,79.681 r270 bottom
SB39 "" SOLDER-BRIDGE_R0603-0R 19.3,79.371 r180 bottom
SB40 "" SOLDER-BRIDGE_R0603-0R 29.37,77.581 r270 bottom
SB41 "" SOLDER-BRIDGE_R0603-0R 27.87,77.581 r270 bottom
SB42 "" SOLDER-BRIDGE_R0603-0R 19.3,77.95 r180 bottom
SB43 "" SOLDER-BRIDGE_R0603-0R 51.97,76.481 r90 bottom
SB44 "" SOLDER-BRIDGE_R0603-0R 19.3,68.2 r0 bottom
SB45 "" SOLDER-BRIDGE_R0603-0R 41.9,87.075 r270 bottom
SB46 "" SOLDER-BRIDGE_R0603-0R 19.3,65.425 r0 bottom
SB47 "" SOLDER-BRIDGE_R0603-0R 38.07,63.581 r90 bottom
SB48 "" SOLDER-BRIDGE_R0603-0R 39.57,63.581 r90 bottom
SB49 "" SOLDER-BRIDGE_R0603-0R 37.202,60.381 r90 bottom
SB50 "" SOLDER-BRIDGE_R0603-0R 27.27,60.881 r0 bottom
SB51 "" SOLDER-BRIDGE_R0603-0R 31.17,60.181 r90 bottom
SB52 "" SOLDER-BRIDGE_R0603-0R 29.737,60.181 r90 bottom
SB53 "" SOLDER-BRIDGE_R0603-0R 52.37,59.5 r270 bottom
SB54 "" SOLDER-BRIDGE_R0603-0R 50.97,55.181 r270 bottom
SB55 "" SOLDER-BRIDGE_R0603-0R 49.37,55.181 r270 bottom
SB56 "" SOLDER-BRIDGE_R0603-0R 47.97,55.181 r270 bottom
SB57 "" SOLDER-BRIDGE_R0603-0R 46.57,55.181 r270 bottom
SB58 "" SOLDER-BRIDGE_R0603-0R 26.17,55.081 r90 bottom
SB59 "" SOLDER-BRIDGE_R0603-0R 24.67,55.081 r90 bottom
SB60 "" SOLDER-BRIDGE_R0603-0R 23.17,55.081 r270 bottom
SB61 "" SOLDER-BRIDGE_R0603-0R 51.245,50.631 r0 bottom
SB62 "" SOLDER-BRIDGE_R0603-0R 51.245,49.131 r180 bottom
SB63 "" SOLDER-BRIDGE_R0603-0R 44.47,47.581 r270 bottom
SB64 "" SOLDER-BRIDGE_R0603-0R 42.97,47.581 r270 bottom
SB65 "" SOLDER-BRIDGE_R0603-0R 41.47,47.581 r90 bottom
SB66 "" SOLDER-BRIDGE_R0603-0R 51.245,47.581 r0 bottom
SB67 "" SOLDER-BRIDGE_R0603-0R 51.245,46.081 r180 bottom
SB68 "" SOLDER-BRIDGE_R0603-0R 51.245,44.581 r0 bottom
SB69 "" SOLDER-BRIDGE_R0603-0R 51.245,43.081 r180 bottom
SB70 "" SOLDER-BRIDGE_R0603-0R 51.245,41.581 r0 bottom
SB71 "" SOLDER-BRIDGE_R0603-0R 51.245,40.081 r180 bottom
SB72 "" SOLDER-BRIDGE_R0603-0R 58.77,19.281 r180 bottom
SB73 "" SOLDER-BRIDGE_R0603-0R 58.77,17.781 r0 bottom
TP1 "Test_Point_PTH_1mm_2mm" TP_PTH_1MM_2MM 62.7,123.9 r0 top value=TP
TP2 "Test_Point_PTH_1mm_2mm" TP_PTH_1MM_2MM 40.9,120.7 r0 top value=TP
TP3 "Test_Point_PTH_1mm_2mm" TP_PTH_1MM_2MM 66.55,112.5 r0 top value=TP
TP4 "Test_Point_PTH_1mm_2mm" TP_PTH_1MM_2MM 43.95,109.75 r0 top value=TP
TP5 "Test_Point_PTH_1mm_2mm" TP_PTH_1MM_2MM 51.495,98.456 r0 top value=TP
U1 "SN74LVC2T45DCUT" ICC_VSSOP8_DCU_R-PDSO-G8_2X2P30_P050 9.866,129.729 r180 top
U2 "TPS2051C" MOS_SOT23-5L 39.916,129.114 r180 top
U3 "ECMF02-2AMX6" ESD_QFN-6L_1P7X1P5_P050 49.541,126.504 r0 top
U4 "ESD-TRANSIL" ESD_QFN2_1P6X1_P125 52.024,126.293 r0 top value=ESDA7P60-1U1M
U5 "ESDALC6V1W5" ESD_SOT323-5L 17.575,124.9 r0 top
U6 "ST-LINKV3E_SWD" ICC_UFBGA201_176+25_10X10_P065 29.066,119.904 r90 top
U7 "ESDALC6V1W5" ESD_SOT323-5L 14.616,120.654 r270 top
U8 "LD3985M33R" REG_SOT23-5L 45.291,117.829 r90 top
U9 "SN74LVC2T45DCUT" ICC_VSSOP8_DCU_R-PDSO-G8_2X2P30_P050 16.991,111.454 r90 top
U10 "" ICC_DFN6-EPAD_3X3_P095 47.545,106.771 r180 top value=LD39050PU33R
U11 "" REG_SOT223-TAB 21.157,103.379 r270 top value=LD1117S50TR
U12 "" ICC_FLIP-CHIP-BGA8_1P11X1P41_P040 45.307,99.356 r0 top value=ST1PS01EJR
U13 "STM32U575ZIT6QU" ICC_LQFP144_20X20_P050_SOCKET_YAMAICHI_IC149-144-145-B5_NM 35.087,71.121 r90 top value=STM32U575ZIT6Q
U14 "USBLC6-2SC6" ESD_SOT23-6L 45.27,14.381 r180 top
U15 "TCPP01-M12" ICC_QFN12L-EPAD_3X3_P050 35.97,12.881 r270 top
U16 "ESD-TRANSIL" ESD_QFN1610_2N_1K_2A 50.77,12.381 r0 top value=ESDA25P35-1U1M
U17 "" ESD_ST0201 57.67,10.981 r90 top value=ESDALC6V1-1U2
U18 "" ESD_ST0201 10.07,9.981 r0 top value=ESDALC6V1-1U2
U19 "" ICC_WLCSP9_1P65X1P87_P050 45.295,99.156 r180 bottom value=ADP5301ACBZ-2-R7
X1 "OSCILLATOR_4_PINS" OSC_NDK_NZ2520SB_4P 29.041,110.904 r90 top value="NZ2520SH 25MHz"
X2 "XTAL_2_PINS" CRY_NX1610SE_2P 30.025,52.375 r180 top value="NX1610SE 32.768kHz"
X3 "XTAL_4_PINS" CRY_NX2016SA_4P 37.517,52.146 r0 top value="NX2016SA 16MHz"

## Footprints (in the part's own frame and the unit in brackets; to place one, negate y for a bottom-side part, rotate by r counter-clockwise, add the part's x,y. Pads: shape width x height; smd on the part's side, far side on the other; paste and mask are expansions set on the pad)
C0402 [mm]
  rect 0.51x0.56 smd mask+0.05: 1(-0.45,0) 2(0.45,0)
  silkscreen extent 0,-0.3 0,0.3, body extent -0.5,-0.3 0.5,0.3, height 0.4
C0603 [mm]
  rect 0.64x0.89 smd mask+0.05: 1(-0.7,0) 2(0.7,0)
  silkscreen extent -1.05,-0.55 1.02,0.55, body extent -0.9,-0.5 0.9,0.5, height 1.4
C0805 [mm]
  rect 0.9x1.4 smd mask+0.05: 1(-0.85,0) 2(0.85,0)
  silkscreen extent -1.3,-0.77 1.3,0.77, body extent -1.1,-0.7 1.1,0.7, height 1.35
CON_SAMTEC_SSW-108-23-X-D_N144_ARD [mm] "NUCLEO144_ARDUINO CONNECTOR"
  rect 1.85x1.85 / inner round 1.85 / far side rect 1.85x1.85 hole 1.1 mask+0.05: 1(8.89,1.27)
  round 1.85 hole 1.1 mask+0.05: 2(8.89,-1.27) 3(6.35,1.27) 4(6.35,-1.27) 5(3.81,1.27) 6(3.81,-1.27) 7(1.27,1.27) 8(1.27,-1.27) 9(-1.27,1.27) 10(-1.27,-1.27) 11(-3.81,1.27) 12(-3.81,-1.27) 13(-6.35,1.27) 14(-6.35,-1.27) 15(-8.89,1.27) 16(-8.89,-1.27)
  silkscreen extent -10.42,-2.47 10.42,2.47, body extent -10.42,-2.48 10.42,2.48, height 8.51
CON_SAMTEC_SSW-110-23-X-D_N144_ARD [mm] "NUCLEO144_ARDUINO CONNECTOR"
  rect 1.85x1.85 / inner round 1.85 / far side rect 1.85x1.85 hole 1.1 mask+0.05: 1(11.43,1.27)
  round 1.85 hole 1.1 mask+0.05: 2(11.43,-1.27) 3(8.89,1.27) 4(8.89,-1.27) 5(6.35,1.27) 6(6.35,-1.27) 7(3.81,1.27) 8(3.81,-1.27) 9(1.27,1.27) 10(1.27,-1.27) 11(-1.27,1.27) 12(-1.27,-1.27) 13(-3.81,1.27) 14(-3.81,-1.27) 15(-6.35,1.27) 16(-6.35,-1.27) 17(-8.89,1.27) 18(-8.89,-1.27) 19(-11.43,1.27) 20(-11.43,-1.27)
  silkscreen extent -12.96,-2.47 12.96,2.47, body extent -12.96,-2.48 12.96,2.48, height 8.51
CON_SAMTEC_SSW-115-23-X-D_N144_ARD [mm] "NUCLEO144_ARDUINO CONNECTOR"
  rect 1.85x1.85 / inner round 1.85 / far side rect 1.85x1.85 hole 1.1 mask+0.05: 1(17.78,1.27)
  round 1.85 hole 1.1 mask+0.05: 2(17.78,-1.27) 3(15.24,1.27) 4(15.24,-1.27) 5(12.7,1.27) 6(12.7,-1.27) 7(10.16,1.27) 8(10.16,-1.27) 9(7.62,1.27) 10(7.62,-1.27) 11(5.08,1.27) 12(5.08,-1.27) 13(2.54,1.27) 14(2.54,-1.27) 15(0,1.27) 16(0,-1.27) 17(-2.54,1.27) 18(-2.54,-1.27) 19(-5.08,1.27) 20(-5.08,-1.27) 21(-7.62,1.27) 22(-7.62,-1.27) 23(-10.16,1.27) 24(-10.16,-1.27) 25(-12.7,1.27) 26(-12.7,-1.27) 27(-15.24,1.27) 28(-15.24,-1.27) 29(-17.78,1.27) 30(-17.78,-1.27)
  silkscreen extent -19.31,-2.47 19.31,2.47, body extent -19.31,-2.48 19.31,2.48, height 8.51
CON_SAMTEC_SSW-117-23-X-D_N144_ARD [mm] "NUCLEO144_ARDUINO CONNECTOR"
  rect 1.85x1.85 / inner round 1.85 / far side rect 1.85x1.85 hole 1.1 mask+0.05: 1(20.32,1.27)
  round 1.85 hole 1.1 mask+0.05: 2(20.32,-1.27) 3(17.78,1.27) 4(17.78,-1.27) 5(15.24,1.27) 6(15.24,-1.27) 7(12.7,1.27) 8(12.7,-1.27) 9(10.16,1.27) 10(10.16,-1.27) 11(7.62,1.27) 12(7.62,-1.27) 13(5.08,1.27) 14(5.08,-1.27) 15(2.54,1.27) 16(2.54,-1.27) 17(0,1.27) 18(0,-1.27) 19(-2.54,1.27) 20(-2.54,-1.27) 21(-5.08,1.27) 22(-5.08,-1.27) 23(-7.62,1.27) 24(-7.62,-1.27) 25(-10.16,1.27) 26(-10.16,-1.27) 27(-12.7,1.27) 28(-12.7,-1.27) 29(-15.24,1.27) 30(-15.24,-1.27) 31(-17.78,1.27) 32(-17.78,-1.27) 33(-20.32,1.27) 34(-20.32,-1.27)
  silkscreen extent -21.85,-2.47 21.85,2.47, body extent -21.85,-2.48 21.85,2.48, height 8.51
CON_SAMTEC_TSW-102-07-G-S [mm]
  rect 1.85x1.85 / inner round 1.85 / far side rect 1.85x1.85 hole 1 mask+0.05: 1(-1.27,0)
  round 1.85 hole 1 mask+0.05: 2(1.27,0)
  silkscreen extent -2.58,-1.3 2.58,1.3, body extent -2.67,-1.3 2.58,1.3, height 8.38
CON_SAMTEC_TSW-102-09-X-S [mm]
  rect 1.85x1.85 / inner round 1.85 / far side rect 1.85x1.85 hole 1 mask+0.05: 1(-1.27,0)
  round 1.85 hole 1 mask+0.05: 2(1.27,0)
  silkscreen extent -2.64,-1.37 2.64,1.37, body extent -2.67,-1.3 2.58,1.3, height 8.38
CON_SAMTEC_TSW-103-07-F-S [mm]
  rect 1.85x1.85 / inner round 1.85 / far side rect 1.85x1.85 hole 1 mask+0.05: 1(-2.54,0)
  round 1.85 hole 1 mask+0.05: 2(0,0) 3(2.54,0)
  silkscreen extent -3.85,-1.3 3.85,1.3, body extent -3.91,-1.37 3.91,1.37, height 8.38
CON_SAMTEC_TSW-104-07-G-S [mm]
  rect 1.85x1.85 / inner round 1.85 / far side rect 1.85x1.85 hole 1 mask+0.05: 1(-3.81,0)
  round 1.85 hole 1 mask+0.05: 2(-1.27,0) 3(1.27,0) 4(3.81,0)
  silkscreen extent -5.12,-1.3 5.12,1.3, body extent -5.21,-1.37 5.18,1.37, height 8.38
CON_SAMTEC_TSW-105-07-X-D [mm]
  rect 1.85x1.85 / inner round 1.85 / far side rect 1.85x1.85 hole 1 mask+0.05: 1(-5.08,-1.27)
  round 1.85 hole 1 mask+0.05: 2(-5.08,1.27) 3(-2.54,-1.27) 4(-2.54,1.27) 5(0,-1.27) 6(0,1.27) 7(2.54,-1.27) 8(2.54,1.27) 9(5.08,-1.27) 10(5.08,1.27)
  silkscreen extent -6.35,-2.54 6.35,2.54, body extent -6.35,-2.54 6.35,2.55, height 8.38
CON_SAMTEC_TSW-135-07-X-D [mm]
  rect 1.85x1.85 / inner round 1.85 / far side rect 1.85x1.85 hole 1 mask+0.05: 1(-43.18,-1.27)
  round 1.85 hole 1 mask+0.05: 2(-43.18,1.27) 3(-40.64,-1.27) 4(-40.64,1.27) 5(-38.1,-1.27) 6(-38.1,1.27) 7(-35.56,-1.27) 8(-35.56,1.27) 9(-33.02,-1.27) 10(-33.02,1.27) 11(-30.48,-1.27) 12(-30.48,1.27) 13(-27.94,-1.27) 14(-27.94,1.27) 15(-25.4,-1.27) 16(-25.4,1.27) 17(-22.86,-1.27) 18(-22.86,1.27) 19(-20.32,-1.27) 20(-20.32,1.27) 21(-17.78,-1.27) 22(-17.78,1.27) 23(-15.24,-1.27) 24(-15.24,1.27) 25(-12.7,-1.27) 26(-12.7,1.27) 27(-10.16,-1.27) 28(-10.16,1.27) 29(-7.62,-1.27) 30(-7.62,1.27) 31(-5.08,-1.27) 32(-5.08,1.27) 33(-2.54,-1.27) 34(-2.54,1.27) 35(0,-1.27) 36(0,1.27) 37(2.54,-1.27) 38(2.54,1.27) 39(5.08,-1.27) 40(5.08,1.27) 41(7.62,-1.27) 42(7.62,1.27) 43(10.16,-1.27) 44(10.16,1.27) 45(12.7,-1.27) 46(12.7,1.27) 47(15.24,-1.27) 48(15.24,1.27) 49(17.78,-1.27) 50(17.78,1.27) 51(20.32,-1.27) 52(20.32,1.27) 53(22.86,-1.27) 54(22.86,1.27) 55(25.4,-1.27) 56(25.4,1.27) 57(27.94,-1.27) 58(27.94,1.27) 59(30.48,-1.27) 60(30.48,1.27) 61(33.02,-1.27) 62(33.02,1.27) 63(35.56,-1.27) 64(35.56,1.27) 65(38.1,-1.27) 66(38.1,1.27) 67(40.64,-1.27) 68(40.64,1.27) 69(43.18,-1.27) 70(43.18,1.27)
  silkscreen extent -44.45,-2.54 44.45,2.54, body extent -44.45,-2.54 44.45,2.54, height 8.38
CON_STDC14_Receiver_MEDIUM_WITH_MIPI10_3D [mm] "compatible with FTSH-105-01-L-DV,-K and FTSH-107-01-L-DV,-K,-A,-P,-ES"
  round 0 hole 1.19 unplated mask+0.05: 0(-5.445,0) 0(5.445,0)
  round 0 hole 0.97 unplated mask+0.05: 0(-3.175,0) 0(3.175,0)
  rect 0.74x2.79 smd mask+0.05: 1(-3.81,-2.032) 2(-3.81,2.032) 3(-2.54,-2.032) 4(-2.54,2.032) 5(-1.27,-2.032) 6(-1.27,2.032) 7(0,-2.032) 8(0,2.032) 9(1.27,-2.032) 10(1.27,2.032) 11(2.54,-2.032) 12(2.54,2.032) 13(3.81,-2.032) 14(3.81,2.032)
  silkscreen extent -6.3,-4.38 6.3,3.6, body extent -6.3,-2.92 6.3,2.92, height 6.6
CON_USB-TYPEC_COXOC_317JD24BZTF3K3C3 [mm]
  rect 0.3x1.2 smd mask+0.05: A1(-2.75,10.58) A2(-2.25,10.58) A3(-1.75,10.58) A4(-1.25,10.58) A5(-0.75,10.58) A6(-0.25,10.58) A7(0.25,10.58) A8(0.75,10.58) A9(1.25,10.58) A10(1.75,10.58) A11(2.25,10.58) A12(2.75,10.58)
  round 0.6 hole 0.4 mask+0.05: B1(2,9.33) B1(2.8,9.33) B2(2.4,8.62) B3(1.6,8.62) B4(1.2,9.33) B5(0.8,8.62) B6(0.4,9.33) B7(-0.4,9.33) B8(-0.8,8.62) B9(-1.2,9.33) B10(-1.6,8.62) B11(-2.4,8.62) B12(-2.8,9.33) B12(-2,9.33)
  oval 1.15x1.55 hole 0.45 slot 0.85 at 90 deg mask+0.05: SH1(-4.27,8.18) SH2(-4.27,3.45) SH3(4.27,8.18) SH4(4.27,3.45)
  silkscreen extent -4.38,-0.95 4.38,10.38, body extent -4.38,-0.95 4.38,10.84, height 3.03
CON_USBMICROB_MOLEX_105017-0001_H2P90 [mm]
  rect 0.4x1.35 smd mask+0.05: 1(-1.3,4.15) 2(-0.65,4.15) 3(0,4.15) 4(0.65,4.15) 5(1.3,4.15)
  round 1.5 hole 0.9 mask+0.05: 6(-2.5,4.15) 7(2.5,4.15)
  oval 1.2x1.9 hole 0.6 slot 1.3 at 90 deg mask+0.05: 8(3.5,1.45) 9(-3.5,1.45)
  rect 1.5x1.9 smd mask+0.05: 10(-1,1.45) 11(1,1.45)
  Top Layer region: 2.3,2.4 3.5,2.4 3.5,0.5 2.3,0.5 2.3,2.4
  Top Layer region: -3.5,2.4 -2.3,2.4 -2.3,0.5 -3.5,0.5 -3.5,2.4
  silkscreen extent -4,-0.7 4,4.6, body extent -4.1,-1.15 4.1,4.66, height 2.9
CRY_NX1610SE_2P [mm] "MCD-02291"
  rect 0.5x1 smd mask+0.05: 1(-0.55,0) 2(0.55,0)
  silkscreen extent -0.13,-0.5 0.13,0.5, body extent -0.8,-0.5 0.8,0.5, height 0.45
CRY_NX2016SA_4P [mm]
  rect 0.85x0.75 smd mask+0.05: 1(-0.675,-0.525) 2(0.675,-0.525) 3(0.675,0.525) 4(-0.675,0.525)
  silkscreen extent -1.22,-1.02 1.05,0.85, body extent -1.05,-0.85 1.05,0.85, height 0.7
DIO_SOD323 [mm]
  rect 1.06x0.54 smd mask+0.05: 1(-1.07,0) 2(1.07,0)
  silkscreen extent -0.9,-0.72 0.9,0.72, body extent -1.3,-0.78 1.3,0.78, height 1.17
DIO_SOD523_1A_2K [mm] "MCD-01677"
  rect 0.65x0.3 smd mask+0.05: 1(-0.675,0) 2(0.675,0)
  silkscreen extent -0.65,-0.45 1.05,0.55, body extent -0.85,-0.45 0.85,0.45, height 0.71
ESD_QFN2_1P6X1_P125 [mm]
  rect 0.55x0.8 smd mask+0.05: 1(-0.625,0) 2(0.625,0)
  silkscreen extent -1,-0.55 0.85,0.55, body extent -0.85,-0.55 0.85,0.55, height 0.61
ESD_QFN1610_2N_1K_2A [mm] "DFN, 2-Leads, Body 1.60x1.00mm"
  rect 0.55x0.9 smd mask+0.05: 1(-0.625,0) 2(0.625,0)
  silkscreen extent -1.02,-0.58 0.85,0.58, body extent -0.85,-0.55 0.85,0.55, height 0.6
ESD_QFN-6L_1P7X1P5_P050 [mm]
  rect 0.25x0.6 smd mask+0.05: 1(-0.5,-0.65) 2(0,-0.65) 3(0.5,-0.65) 4(0.5,0.65) 5(0,0.65) 6(-0.5,0.65)
  silkscreen extent -0.9,-0.8 0.9,0.8, body extent -0.9,-0.8 0.9,0.8, height 0.56
ESD_SOT23-6L [mm]
  rect 0.6x1.2 smd mask+0.05: 1(-0.95,-1.15) 2(0,-1.15) 3(0.95,-1.15) 4(0.95,1.15) 5(0,1.15) 6(-0.95,1.15)
  silkscreen extent -1.53,-0.87 1.53,0.87, body extent -1.52,-1.5 1.52,1.5, height 1.45
ESD_SOT323-5L [mm]
  rect 0.4x1.2 smd mask+0.05: 1(-0.65,-0.85) 2(0,-0.85) 3(0.65,-0.85) 4(0.65,0.85) 5(-0.65,0.85)
  silkscreen extent -1.22,-1.21 1.22,0.77, body extent -1.15,-1.05 1.15,1.05, height 1.1
ESD_ST0201 [mm]
  rect 0.425x0.33 smd mask+0.05: 1(-0.312,0) 2(0.312,0)
  silkscreen extent -0.55,-0.3 0.33,0.3, body extent -0.34,-0.18 0.34,0.18, height 0.34
ICC_DFN6-EPAD_3X3_P095 [mm]
  rect 0.45x0.5 smd mask+0.05: 1(-0.95,-1.3) 2(0,-1.3) 3(0.95,-1.3) 4(0.95,1.3) 5(0,1.3) 6(-0.95,1.3)
  rect 2.5x1.7 smd mask+0.05: EP(0,0)
  silkscreen extent -1.55,-1.55 1.55,1.55, body extent -1.55,-1.55 1.55,1.55, height 1
ICC_FLIP-CHIP-BGA8_1P11X1P41_P040 [mm] "MCD-00228"
  round 0.2 smd paste+0.025 mask+0.05: A1(-0.312,0.5) A3(0.312,0.5) B2(0,0.25) C1(-0.312,0) C3(0.312,0) D2(0,-0.25) E1(-0.312,-0.5) E3(0.312,-0.5)
  silkscreen extent -0.7,-0.72 0.57,0.85, body extent -0.57,-0.72 0.57,0.72, height 0.61
ICC_LQFP144_20X20_P050_SOCKET_YAMAICHI_IC149-144-145-B5_NM [mm]
  rect 1x2.5 smd rot 45 mask+0.05: 0(-10.96,-10.96) 0(10.96,10.96)
  rect 1x2.5 smd rot 135 mask+0.05: 0(-10.96,10.96) 0(10.96,-10.96)
  round 0 hole 1.5 unplated mask+0.05: 0(0,8) 0(0,-8)
  rect 1.65x0.5 smd mask+0.05: 1(-10.825,8.85) 36(-10.825,-8.85) 73(10.825,-8.85) 108(10.825,8.85)
  rect 1.65x0.3 smd mask+0.05: 2(-10.825,8.25) 3(-10.825,7.75) 4(-10.825,7.25) 5(-10.825,6.75) 6(-10.825,6.25) 7(-10.825,5.75) 8(-10.825,5.25) 9(-10.825,4.75) 10(-10.825,4.25) 11(-10.825,3.75) 12(-10.825,3.25) 13(-10.825,2.75) 14(-10.825,2.25) 15(-10.825,1.75) 16(-10.825,1.25) 17(-10.825,0.75) 18(-10.825,0.25) 19(-10.825,-0.25) 20(-10.825,-0.75) 21(-10.825,-1.25) 22(-10.825,-1.75) 23(-10.825,-2.25) 24(-10.825,-2.75) 25(-10.825,-3.25) 26(-10.825,-3.75) 27(-10.825,-4.25) 28(-10.825,-4.75) 29(-10.825,-5.25) 30(-10.825,-5.75) 31(-10.825,-6.25) 32(-10.825,-6.75) 33(-10.825,-7.25) 34(-10.825,-7.75) 35(-10.825,-8.25) 74(10.825,-8.25) 75(10.825,-7.75) 76(10.825,-7.25) 77(10.825,-6.75) 78(10.825,-6.25) 79(10.825,-5.75) 80(10.825,-5.25) 81(10.825,-4.75) 82(10.825,-4.25) 83(10.825,-3.75) 84(10.825,-3.25) 85(10.825,-2.75) 86(10.825,-2.25) 87(10.825,-1.75) 88(10.825,-1.25) 89(10.825,-0.75) 90(10.825,-0.25) 91(10.825,0.25) 92(10.825,0.75) 93(10.825,1.25) 94(10.825,1.75) 95(10.825,2.25) 96(10.825,2.75) 97(10.825,3.25) 98(10.825,3.75) 99(10.825,4.25) 100(10.825,4.75) 101(10.825,5.25) 102(10.825,5.75) 103(10.825,6.25) 104(10.825,6.75) 105(10.825,7.25) 106(10.825,7.75) 107(10.825,8.25)
  rect 0.5x1.65 smd mask+0.05: 37(-8.85,-10.825) 72(8.85,-10.825) 109(8.85,10.825) 144(-8.85,10.825)
  rect 0.3x1.65 smd mask+0.05: 38(-8.25,-10.825) 39(-7.75,-10.825) 40(-7.25,-10.825) 41(-6.75,-10.825) 42(-6.25,-10.825) 43(-5.75,-10.825) 44(-5.25,-10.825) 45(-4.75,-10.825) 46(-4.25,-10.825) 47(-3.75,-10.825) 48(-3.25,-10.825) 49(-2.75,-10.825) 50(-2.25,-10.825) 51(-1.75,-10.825) 52(-1.25,-10.825) 53(-0.75,-10.825) 54(-0.25,-10.825) 55(0.25,-10.825) 56(0.75,-10.825) 57(1.25,-10.825) 58(1.75,-10.825) 59(2.25,-10.825) 60(2.75,-10.825) 61(3.25,-10.825) 62(3.75,-10.825) 63(4.25,-10.825) 64(4.75,-10.825) 65(5.25,-10.825) 66(5.75,-10.825) 67(6.25,-10.825) 68(6.75,-10.825) 69(7.25,-10.825) 70(7.75,-10.825) 71(8.25,-10.825) 110(8.25,10.825) 111(7.75,10.825) 112(7.25,10.825) 113(6.75,10.825) 114(6.25,10.825) 115(5.75,10.825) 116(5.25,10.825) 117(4.75,10.825) 118(4.25,10.825) 119(3.75,10.825) 120(3.25,10.825) 121(2.75,10.825) 122(2.25,10.825) 123(1.75,10.825) 124(1.25,10.825) 125(0.75,10.825) 126(0.25,10.825) 127(-0.25,10.825) 128(-0.75,10.825) 129(-1.25,10.825) 130(-1.75,10.825) 131(-2.25,10.825) 132(-2.75,10.825) 133(-3.25,10.825) 134(-3.75,10.825) 135(-4.25,10.825) 136(-4.75,10.825) 137(-5.25,10.825) 138(-5.75,10.825) 139(-6.25,10.825) 140(-6.75,10.825) 141(-7.25,10.825) 142(-7.75,10.825) 143(-8.25,10.825)
  silkscreen extent -10.1,-10.1 10.1,10.1, body extent -11,-11 11,11, height 1.6
ICC_QFN12L-EPAD_3X3_P050 [mm] "MCD-01809"
  rect 0.3x0.75 smd mask+0.05: 1(-0.5,-1.425) 2(0,-1.425) 3(0.5,-1.425) 7(0.5,1.425) 8(0,1.425) 9(-0.5,1.425)
  rect 0.75x0.3 smd mask+0.05: 4(1.425,-0.5) 5(1.425,0) 6(1.425,0.5) 10(-1.425,0.5) 11(-1.425,0) 12(-1.425,-0.5)
  rect 1.7x1.7 smd mask+0.05: 13(0,0)
  silkscreen extent -1.55,-1.55 1.55,1.55, body extent -1.55,-1.55 1.55,1.55, height 0.8
ICC_UFBGA201_176+25_10X10_P065 [mm] "IPC"
  round 0.25 smd mask+0.05: A1(-4.55,4.55) A2(-3.9,4.55) A3(-3.25,4.55) A4(-2.6,4.55) A5(-1.95,4.55) A6(-1.3,4.55) A7(-0.65,4.55) A8(0,4.55) A9(0.65,4.55) A10(1.3,4.55) A11(1.95,4.55) A12(2.6,4.55) A13(3.25,4.55) A14(3.9,4.55) A15(4.55,4.55) B1(-4.55,3.9) B2(-3.9,3.9) B3(-3.25,3.9) B4(-2.6,3.9) B5(-1.95,3.9) B6(-1.3,3.9) B7(-0.65,3.9) B8(0,3.9) B9(0.65,3.9) B10(1.3,3.9) B11(1.95,3.9) B12(2.6,3.9) B13(3.25,3.9) B14(3.9,3.9) B15(4.55,3.9) C1(-4.55,3.25) C2(-3.9,3.25) C3(-3.25,3.25) C4(-2.6,3.25) C5(-1.95,3.25) C6(-1.3,3.25) C7(-0.65,3.25) C8(0,3.25) C9(0.65,3.25) C10(1.3,3.25) C11(1.95,3.25) C12(2.6,3.25) C13(3.25,3.25) C14(3.9,3.25) C15(4.55,3.25) D1(-4.55,2.6) D2(-3.9,2.6) D3(-3.25,2.6) D4(-2.6,2.6) D5(-1.95,2.6) D6(-1.3,2.6) D7(-0.65,2.6) D8(0,2.6) D9(0.65,2.6) D10(1.3,2.6) D11(1.95,2.6) D12(2.6,2.6) D13(3.25,2.6) D14(3.9,2.6) D15(4.55,2.6) E1(-4.55,1.95) E2(-3.9,1.95) E3(-3.25,1.95) E4(-2.6,1.95) E12(2.6,1.95) E13(3.25,1.95) E14(3.9,1.95) E15(4.55,1.95) F1(-4.55,1.3) F2(-3.9,1.3) F3(-3.25,1.3) F4(-2.6,1.3) F6(-1.3,1.3) F7(-0.65,1.3) F8(0,1.3) F9(0.65,1.3) F10(1.3,1.3) F12(2.6,1.3) F13(3.25,1.3) F14(3.9,1.3) F15(4.55,1.3) G1(-4.55,0.65) G2(-3.9,0.65) G3(-3.25,0.65) G4(-2.6,0.65) G6(-1.3,0.65) G7(-0.65,0.65) G8(0,0.65) G9(0.65,0.65) G10(1.3,0.65) G12(2.6,0.65) G13(3.25,0.65) G14(3.9,0.65) G15(4.55,0.65) H1(-4.55,0) H2(-3.9,0) H3(-3.25,0) H4(-2.6,0) H6(-1.3,0) H7(-0.65,0) H8(0,0) H9(0.65,0) H10(1.3,0) H12(2.6,0) H13(3.25,0) H14(3.9,0) H15(4.55,0) J1(-4.55,-0.65) J2(-3.9,-0.65) J3(-3.25,-0.65) J4(-2.6,-0.65) J6(-1.3,-0.65) J7(-0.65,-0.65) J8(0,-0.65) J9(0.65,-0.65) J10(1.3,-0.65) J12(2.6,-0.65) J13(3.25,-0.65) J14(3.9,-0.65) J15(4.55,-0.65) K1(-4.55,-1.3) K2(-3.9,-1.3) K3(-3.25,-1.3) K4(-2.6,-1.3) K6(-1.3,-1.3) K7(-0.65,-1.3) K8(0,-1.3) K9(0.65,-1.3) K10(1.3,-1.3) K12(2.6,-1.3) K13(3.25,-1.3) K14(3.9,-1.3) K15(4.55,-1.3) L1(-4.55,-1.95) L2(-3.9,-1.95) L3(-3.25,-1.95) L4(-2.6,-1.95) L12(2.6,-1.95) L13(3.25,-1.95) L14(3.9,-1.95) L15(4.55,-1.95) M1(-4.55,-2.6) M2(-3.9,-2.6) M3(-3.25,-2.6) M4(-2.6,-2.6) M5(-1.95,-2.6) M6(-1.3,-2.6) M7(-0.65,-2.6) M8(0,-2.6) M9(0.65,-2.6) M10(1.3,-2.6) M11(1.95,-2.6) M12(2.6,-2.6) M13(3.25,-2.6) M14(3.9,-2.6) M15(4.55,-2.6) N1(-4.55,-3.25) N2(-3.9,-3.25) N3(-3.25,-3.25) N4(-2.6,-3.25) N5(-1.95,-3.25) N6(-1.3,-3.25) N7(-0.65,-3.25) N8(0,-3.25) N9(0.65,-3.25) N10(1.3,-3.25) N11(1.95,-3.25) N12(2.6,-3.25) N13(3.25,-3.25) N14(3.9,-3.25) N15(4.55,-3.25) P1(-4.55,-3.9) P2(-3.9,-3.9) P3(-3.25,-3.9) P4(-2.6,-3.9) P5(-1.95,-3.9) P6(-1.3,-3.9) P7(-0.65,-3.9) P8(0,-3.9) P9(0.65,-3.9) P10(1.3,-3.9) P11(1.95,-3.9) P12(2.6,-3.9) P13(3.25,-3.9) P14(3.9,-3.9) P15(4.55,-3.9) R1(-4.55,-4.55) R2(-3.9,-4.55) R3(-3.25,-4.55) R4(-2.6,-4.55) R5(-1.95,-4.55) R6(-1.3,-4.55) R7(-0.65,-4.55) R8(0,-4.55) R9(0.65,-4.55) R10(1.3,-4.55) R11(1.95,-4.55) R12(2.6,-4.55) R13(3.25,-4.55) R14(3.9,-4.55) R15(4.55,-4.55)
  silkscreen extent -5.22,-5.07 5.07,5.23, body extent -5.07,-5.07 5.07,5.07, height 0.61
ICC_VSSOP8_DCU_R-PDSO-G8_2X2P30_P050 [mm]
  rect 0.3x0.8 smd mask+0.05: 1(-0.75,-1.55) 2(-0.25,-1.55) 3(0.25,-1.55) 4(0.75,-1.55) 5(0.75,1.55) 6(0.25,1.55) 7(-0.25,1.55) 8(-0.75,1.55)
  silkscreen extent -1.05,-1.2 1.05,1.2, body extent -1.05,-1.62 1.05,1.62, height 0.9
ICC_WLCSP9_1P65X1P87_P050 [mm]
  round 0.3 smd mask+0.05: A1(-0.5,0.5) A2(0,0.5) A3(0.5,0.5) B1(-0.5,0) B2(0,0) B3(0.5,0) C1(-0.5,-0.5) C2(0,-0.5) C3(0.5,-0.5)
  silkscreen extent -0.97,-0.97 0.85,1.1, body extent -0.85,-0.97 0.85,0.97, height 0.67
IND_TDK_VLS252010HBX-1 [mm]
  rect 0.6x2 smd mask+0.05: 1(-0.95,0) 2(0.95,0)
  silkscreen extent -1.38,-1.12 1.38,1.12, body extent -1.35,-1.1 1.35,1.1, height 1.01
L0805_H0P9 [mm]
  rect 1.1x1.6 smd mask+0.05: 1(-0.75,0) 2(0.75,0)
  silkscreen extent -0.08,-0.7 0.08,0.7, body extent -1.07,-0.7 1.07,0.7, height 1.2
LED_0603_GREEN [mm]
  rect 0.8x0.8 smd mask+0.05: 1(-0.75,0) 2(0.75,0)
  silkscreen extent -0.25,-0.4 1.25,0.4, body extent -0.8,-0.4 0.8,0.4, height 0.6
LED_0603_RED [mm]
  rect 0.8x0.8 smd mask+0.05: 1(-0.75,0) 2(0.75,0)
  silkscreen extent -0.25,-0.4 1.25,0.4, body extent -0.8,-0.4 0.8,0.4, height 0.6
LED_0603_VISHAY_VLMB1300-GS08_BLUE_1A2K_H0P8 [mm]
  rect 0.8x0.8 smd mask+0.05: 1(-0.75,0) 2(0.75,0)
  silkscreen extent -0.85,-0.53 1.28,0.53, body extent -0.85,-0.45 0.85,0.45, height 0.8
LED_BI-GR_HSMF-A201-A00J1 [mm] "MCD-00051"
  rect 1.1x1.5 smd mask+0.05: 1(-0.75,-1.5) 2(-0.75,1.5) 3(0.75,1.5) 4(0.75,-1.5)
  silkscreen extent -1.65,-1.85 1.5,1.7, body extent -1.5,-1.85 1.5,1.85, height 2.1
MIRE_PLACE_SMD_0P8MM [mm]
  round 0.8 smd paste-10 mask+0.2: 1(0,0)
  Top Layer keep-out circle w0.01: c0,0 r0.804
MOS_POWERFLAT_3P3X3P3_P065 [mm] "MCD-01126"
  rect 0.4x0.75 smd mask+0.05: 1(-0.975,-1.525) 2(-0.325,-1.525) 3(0.325,-1.525) 4(0.975,-1.525) 6(0.325,1.525) 7(-0.325,1.525)
  rect 0.45x0.75 smd mask+0.05: 5(1,1.525) 8(-1,1.525)
  Top Layer region: -1.755,0.2 -1.755,-0.2 -1.225,-0.2 -1.225,-0.5 1.225,-0.5 1.225,-0.2 1.755,-0.2 1.755,0.2 1.225,0.2 1.225,1.9 -1.225,1.9 -1.225,0.2
  silkscreen extent -1.63,-1.55 1.63,1.55, body extent -1.75,-1.75 1.75,1.75, height 0.91
MOS_SOT23-5L [mm]
  rect 0.6x1.3 smd mask+0.05: 1(-0.95,-1.1) 2(0,-1.1) 3(0.95,-1.1) 4(0.95,1.1) 5(-0.95,1.1)
  silkscreen extent -1.6,-0.95 1.6,0.97, body extent -1.52,-1.25 1.52,1.25, height 1.45
NPN_SOT23 [mm]
  rect 1x1.4 smd mask+0.05: 1(-0.95,-1.1) 2(0.95,-1.1) 3(0,1.1)
  silkscreen extent -1.63,-0.82 1.63,0.82, body extent -1.56,-1.25 1.56,1.25, height 1.1
OSC_NDK_NZ2520SB_4P [mm]
  rect 1x1 smd mask+0.05: 1(-0.825,-0.625) 2(0.825,-0.625) 3(0.825,0.625) 4(-0.825,0.625)
  silkscreen extent -1.43,-1.22 1.2,1.05, body extent -1.3,-1.05 1.3,1.05, height 0.91
R0402 [mm]
  rect 0.51x0.7 smd mask+0.05: 1(-0.45,0) 2(0.45,0)
  silkscreen extent 0,-0.3 0,0.3, body extent -0.52,-0.3 0.52,0.3, height 0.4
R0603 [mm]
  rect 0.64x1 smd mask+0.05: 1(-0.7,0) 2(0.7,0)
  silkscreen extent -1.05,-0.58 1.05,0.58, body extent -0.9,-0.5 0.9,0.5, height 0.56
REG_SOT23-5L [mm]
  rect 0.6x1.3 smd mask+0.05: 1(-0.95,-1.1) 2(0,-1.1) 3(0.95,-1.1) 4(0.95,1.1) 5(-0.95,1.1)
  silkscreen extent -1.6,-0.95 1.6,0.97, body extent -1.52,-1.25 1.52,1.25, height 1.1
REG_SOT223-TAB [mm]
  rect 1.5x1.65 smd mask+0.05: 1(-2.3,-3.175) 2(0,-3.175) 3(2.3,-3.175)
  rect 3.5x1.65 smd mask+0.05: 4(0,3.175)
  silkscreen extent -3.35,-2.15 3.35,2.12, body extent -3.35,-3.48 3.35,3.48, height 1.8
Sheetbox_6L2S [mil] "Sheetbox 6 layers / 2 silkscreens"
  round 20 on Mech16: 1(813.5,208.05) 1(2736.63,208.05)
SOLDER-BRIDGE_R0603-0R [mil]
  round 10 smd paste-393.7: 1(-19.68,0) 2(23.62,0)
  Top Layer region: -47.24,-19.69 -47.24,19.68 -15.75,19.68 3.94,0 -15.75,-19.69 -47.24,-19.69
  Top Layer region: -5.91,19.68 13.78,0 -5.91,-19.69 47.24,-19.69 47.24,19.68 -5.91,19.68
  silkscreen extent -50,-23 50,23, body extent -36,-20 36,20, height 22
STICKER_25X9 [mm] "Sticker 25mm x 9mm"
  silkscreen extent -12.5,-4.5 12.5,4.5
SWI_WEALTHMETAL_TD-0341_4P_BLACK [mm]
  rect 1.52x2.16 smd mask+0.05: 1(-2.25,-4.75) 2(-2.25,4.75) 3(2.25,-4.75) 4(2.25,4.75)
  silkscreen extent -3,-3.5 3,3.5, body extent -3,-5.15 3,5.15, height 7.55
SWI_WEALTHMETAL_TD-0341_4P_BLUE [mm]
  rect 1.52x2.16 smd mask+0.05: 1(-2.25,-4.75) 2(-2.25,4.75) 3(2.25,-4.75) 4(2.25,4.75)
  silkscreen extent -3,-3.5 3,3.5, body extent -3,-5.15 3,5.15, height 7.55
TP_PTH_1MM_2MM [mm] "MCD-01506"
  round 2 hole 1 mask+0.05: 1(0,0)
  silkscreen extent -1.2,-1.2 1.2,1.2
